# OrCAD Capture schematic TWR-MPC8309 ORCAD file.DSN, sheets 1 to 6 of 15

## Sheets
1 P15:Power Supplies: size C; title: Power Supplies; rev: C; note: TWR-MPC8309
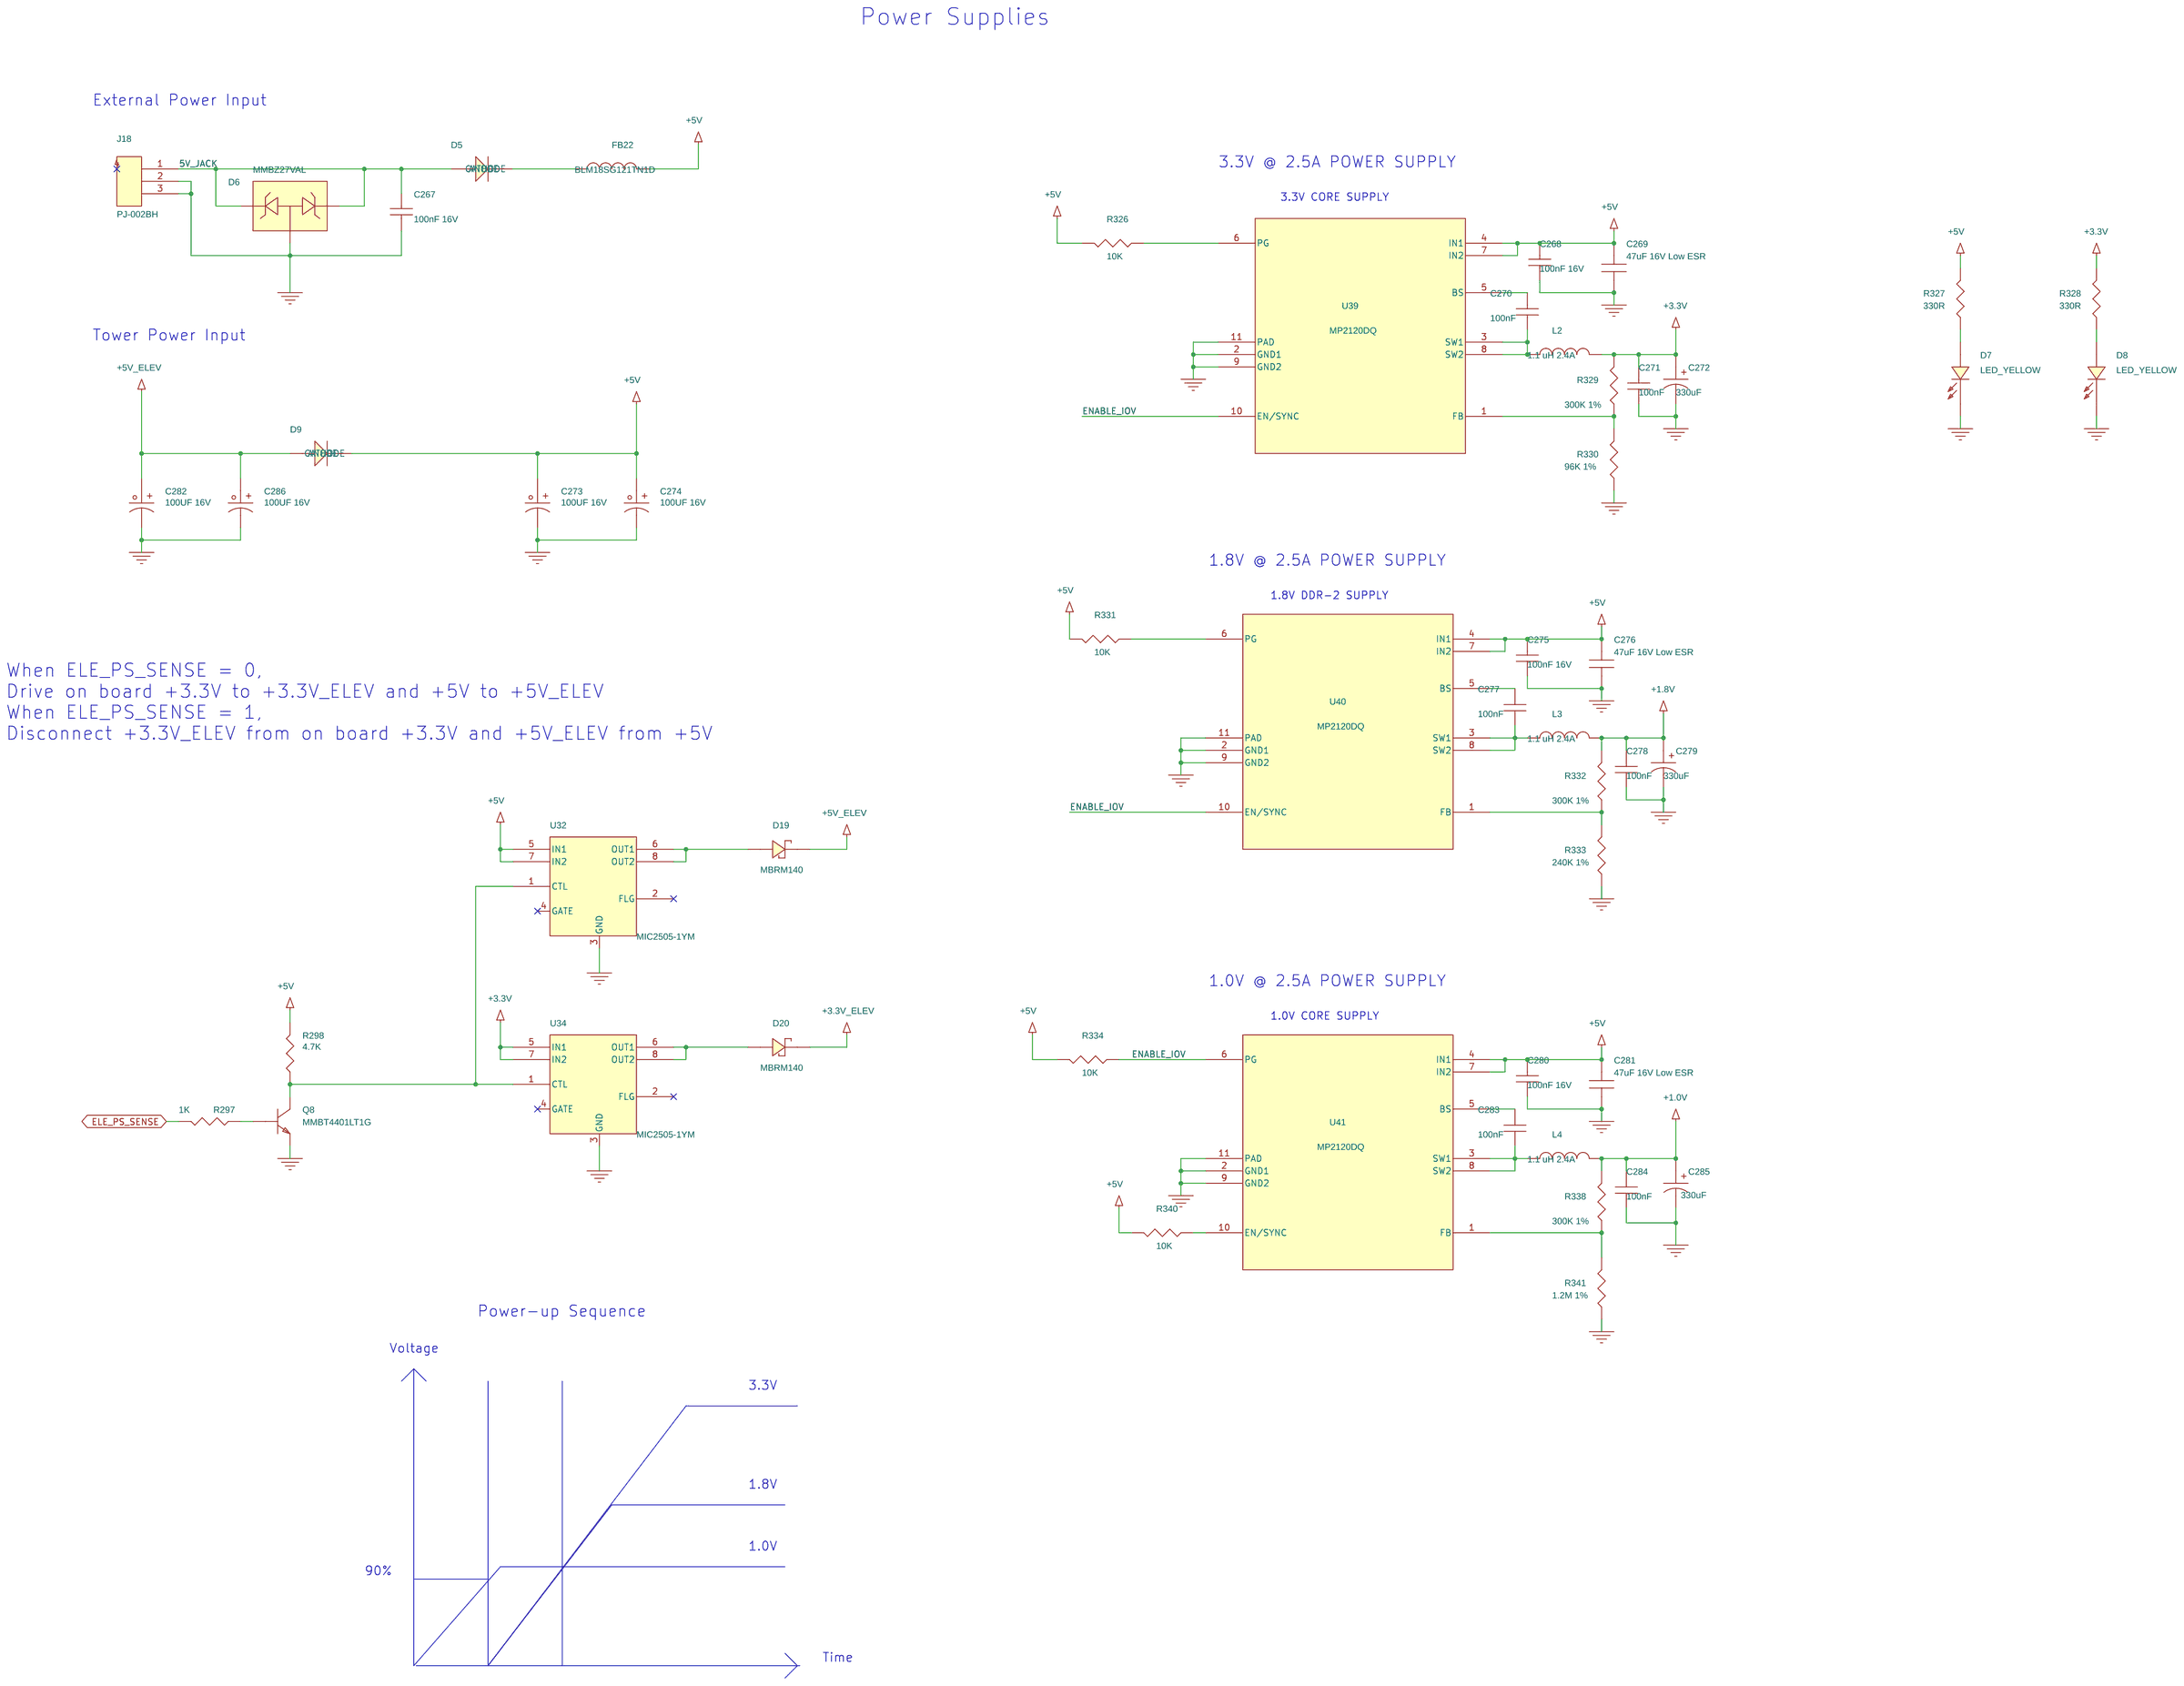
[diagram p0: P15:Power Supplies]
2 P13:Audio CODEC: size C; title: Audio CODEC
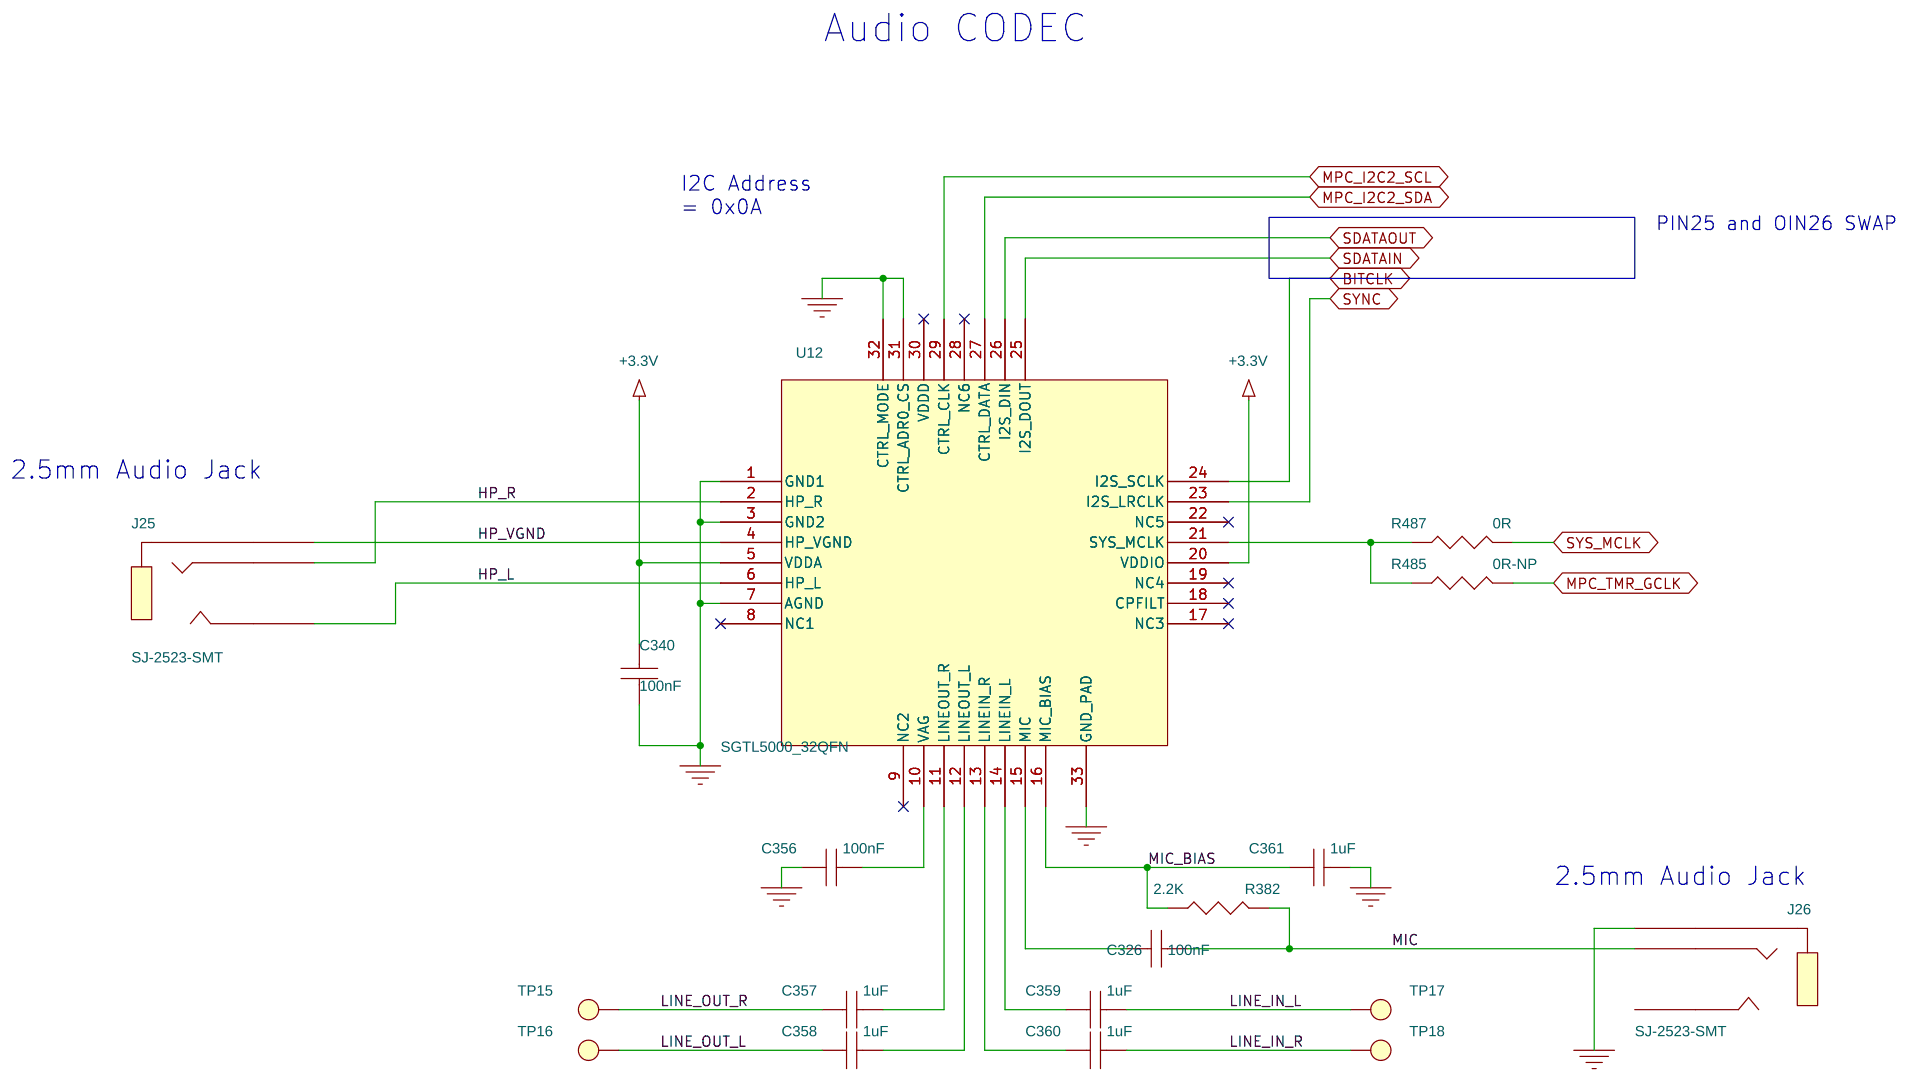
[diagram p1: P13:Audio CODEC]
3 P01:Cover Sheet: title: Cover page
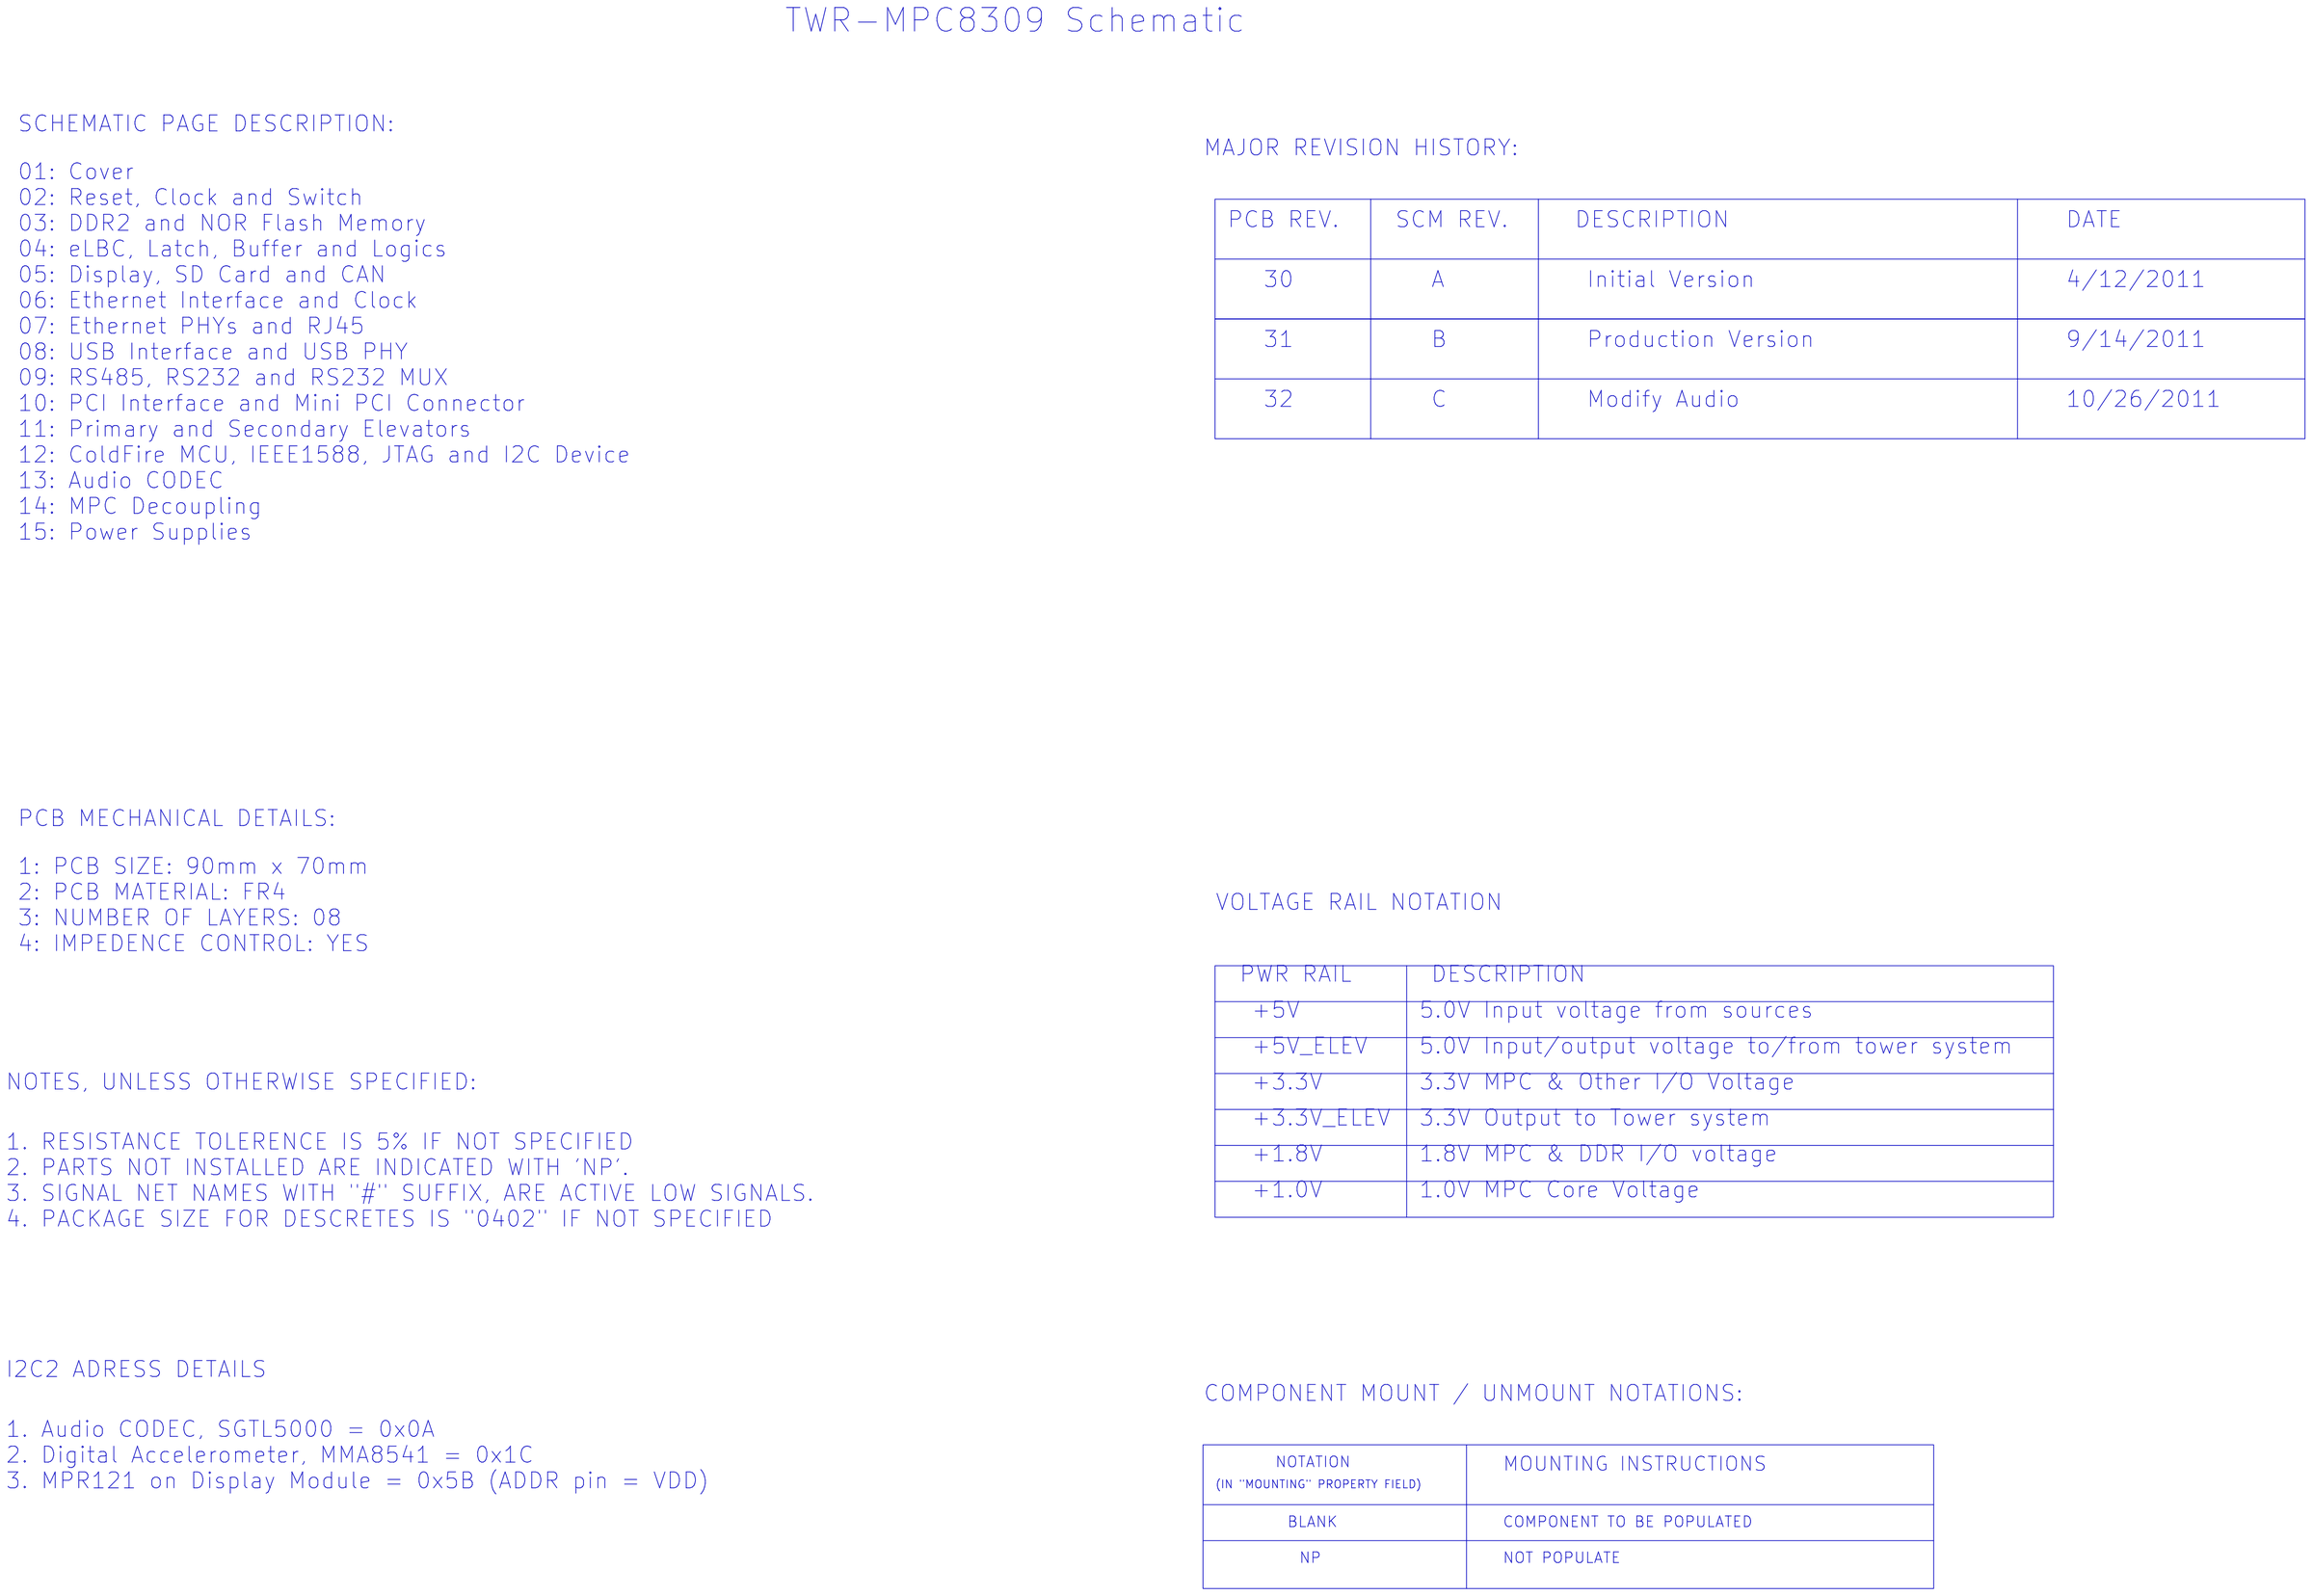
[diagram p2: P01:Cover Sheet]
4 P14:MPC Decoupling: size C; title: MPC Decoupling
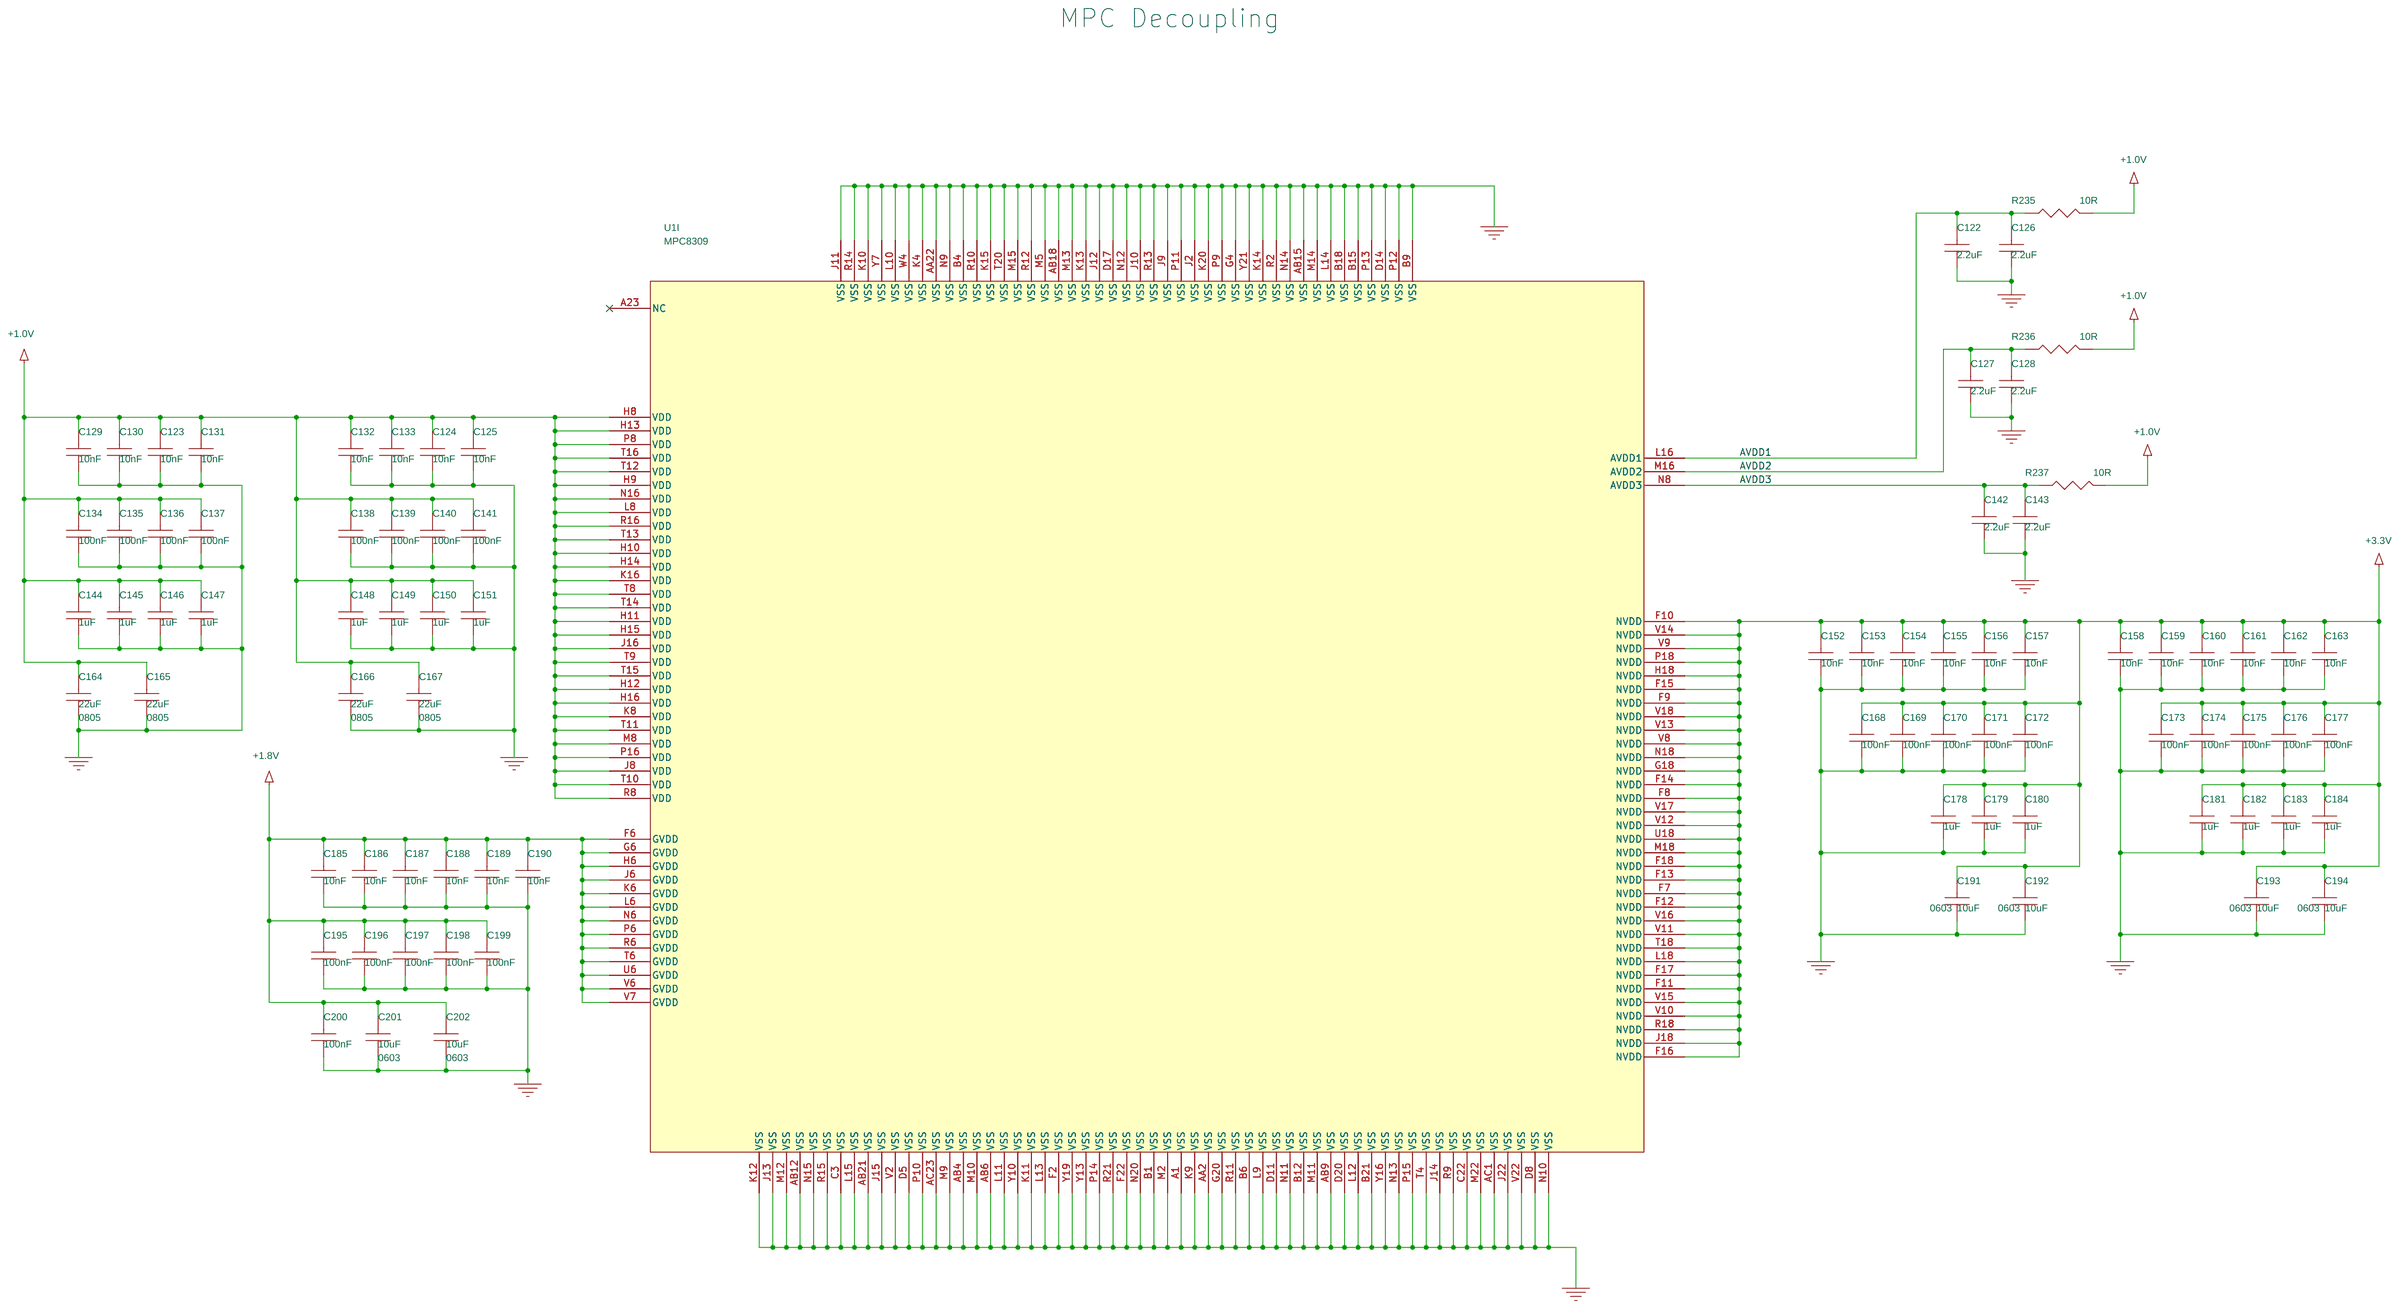
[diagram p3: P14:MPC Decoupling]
5 P05:Display, SD Card & CAN: size C; title: Display, SD card & CAN
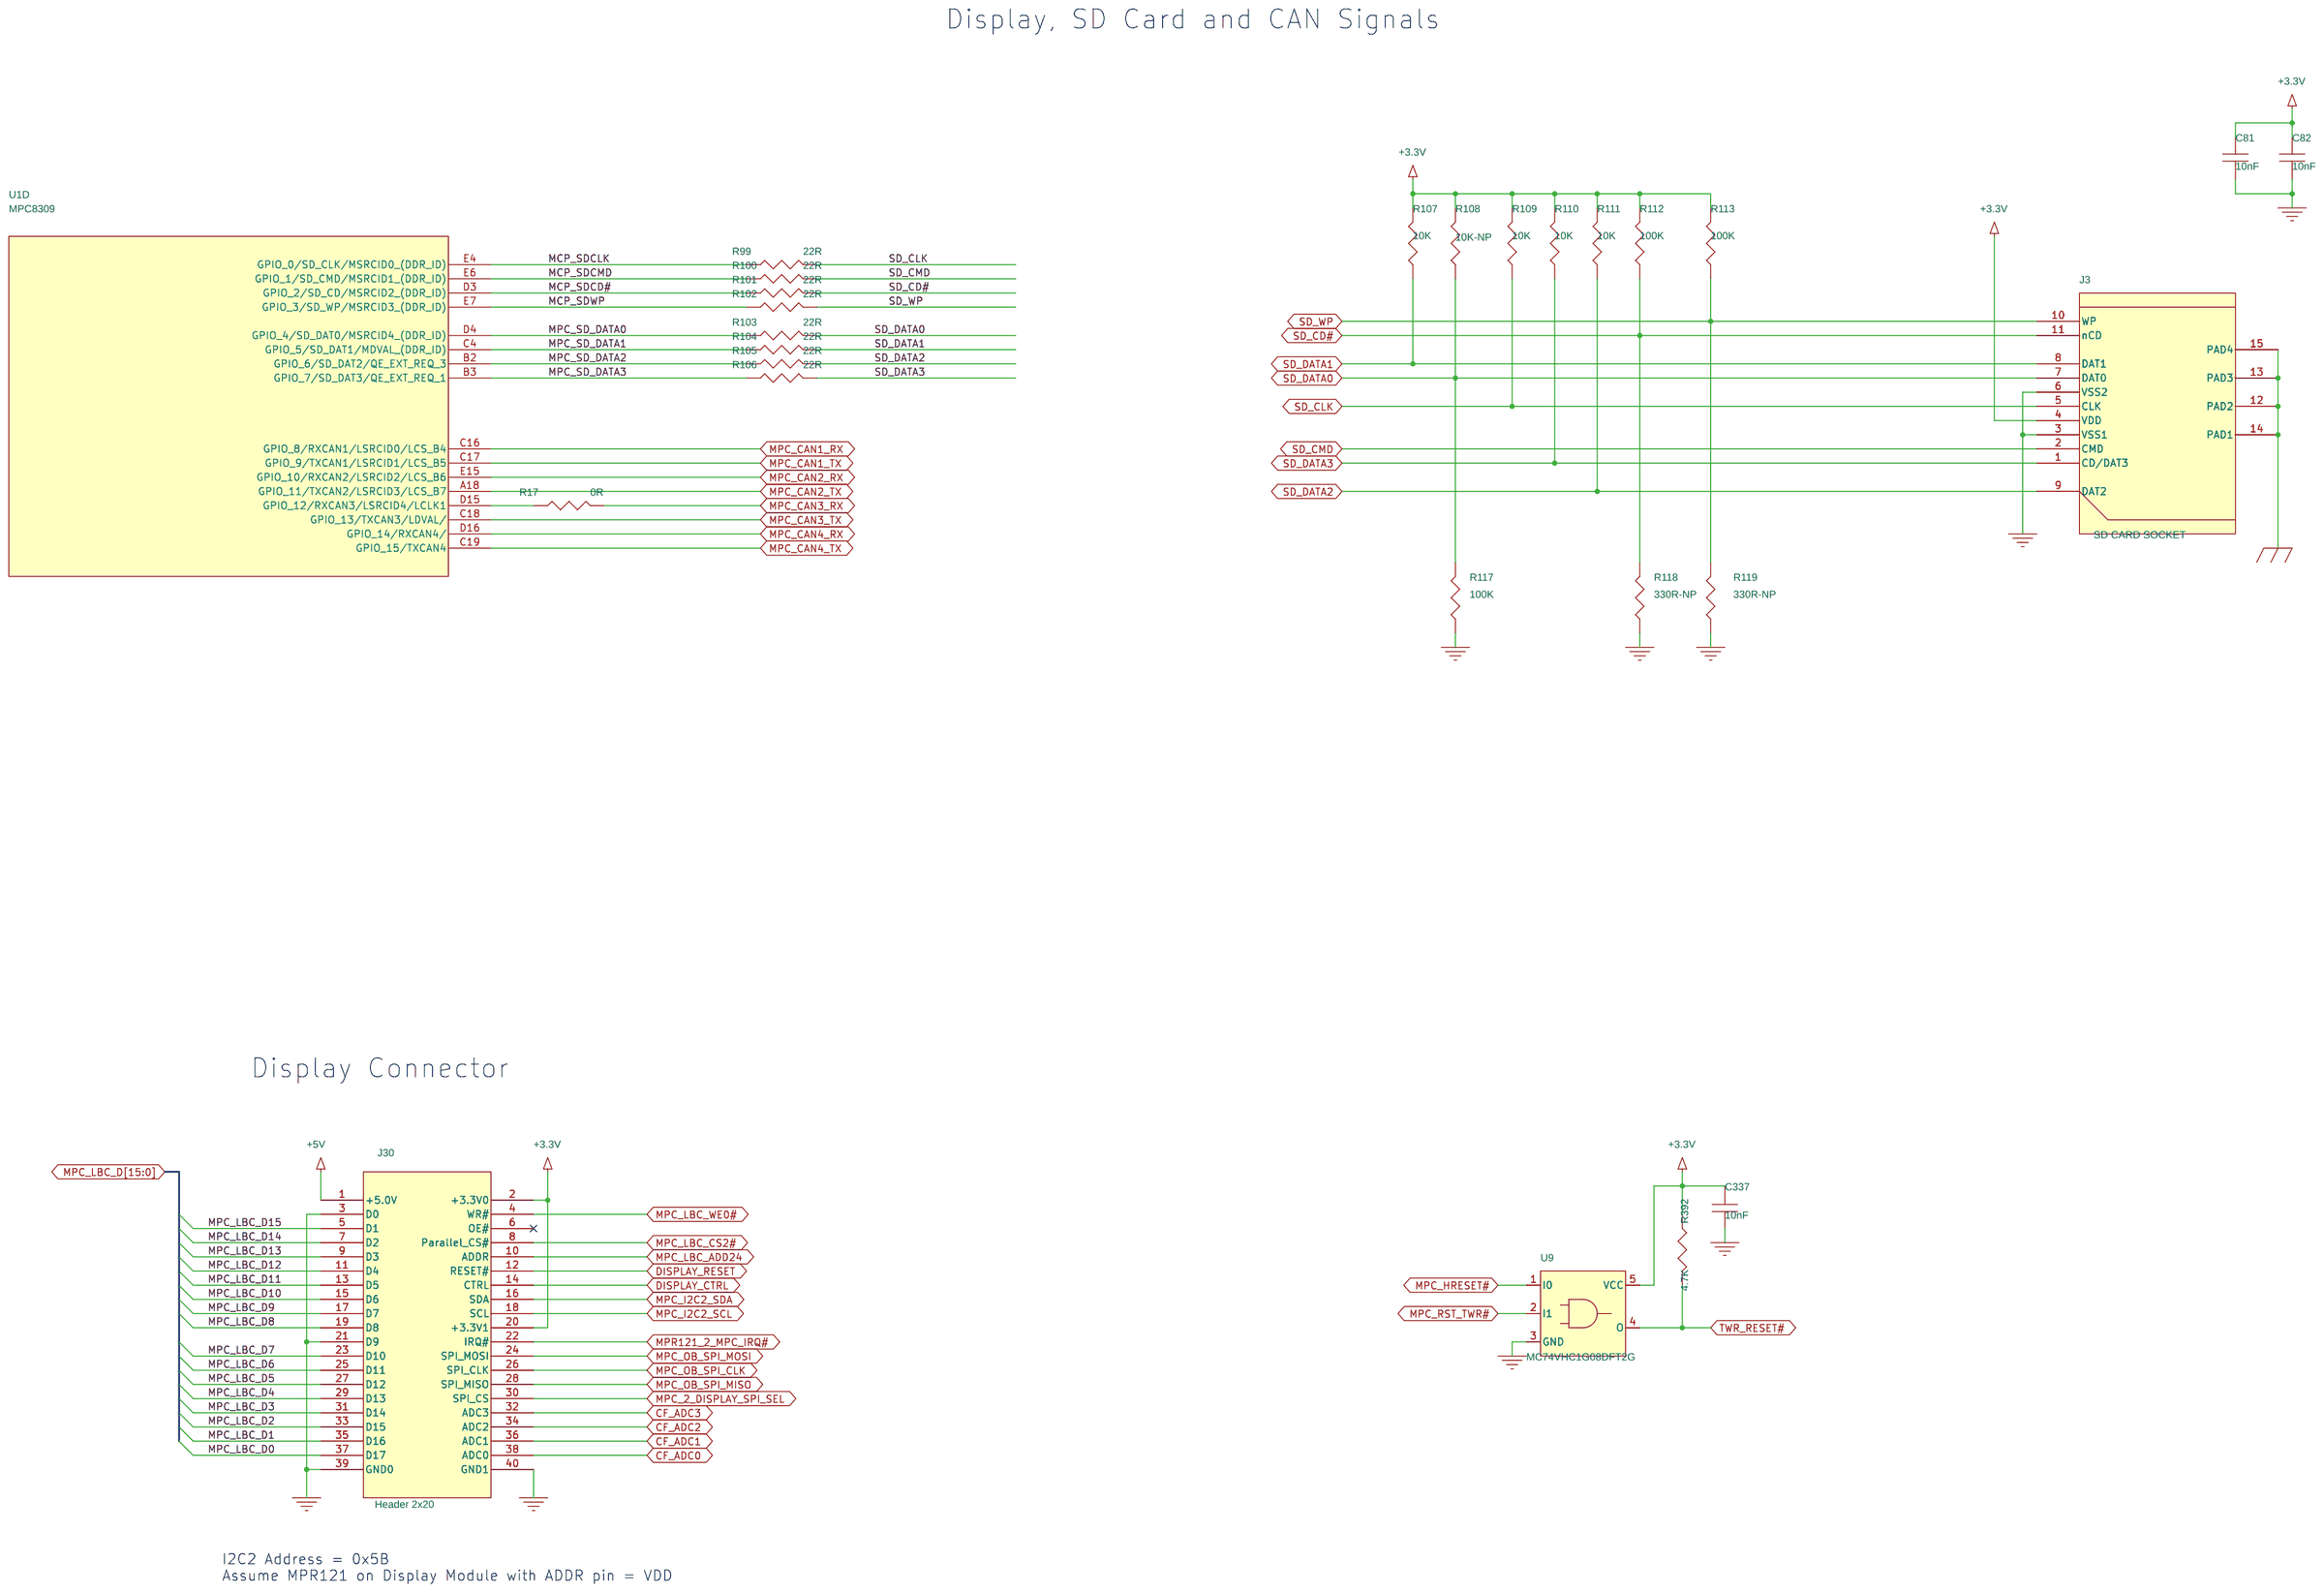
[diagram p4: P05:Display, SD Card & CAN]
6 P11:PRI & SEC Elevators: size C; title: Primary and Secondary Elevator
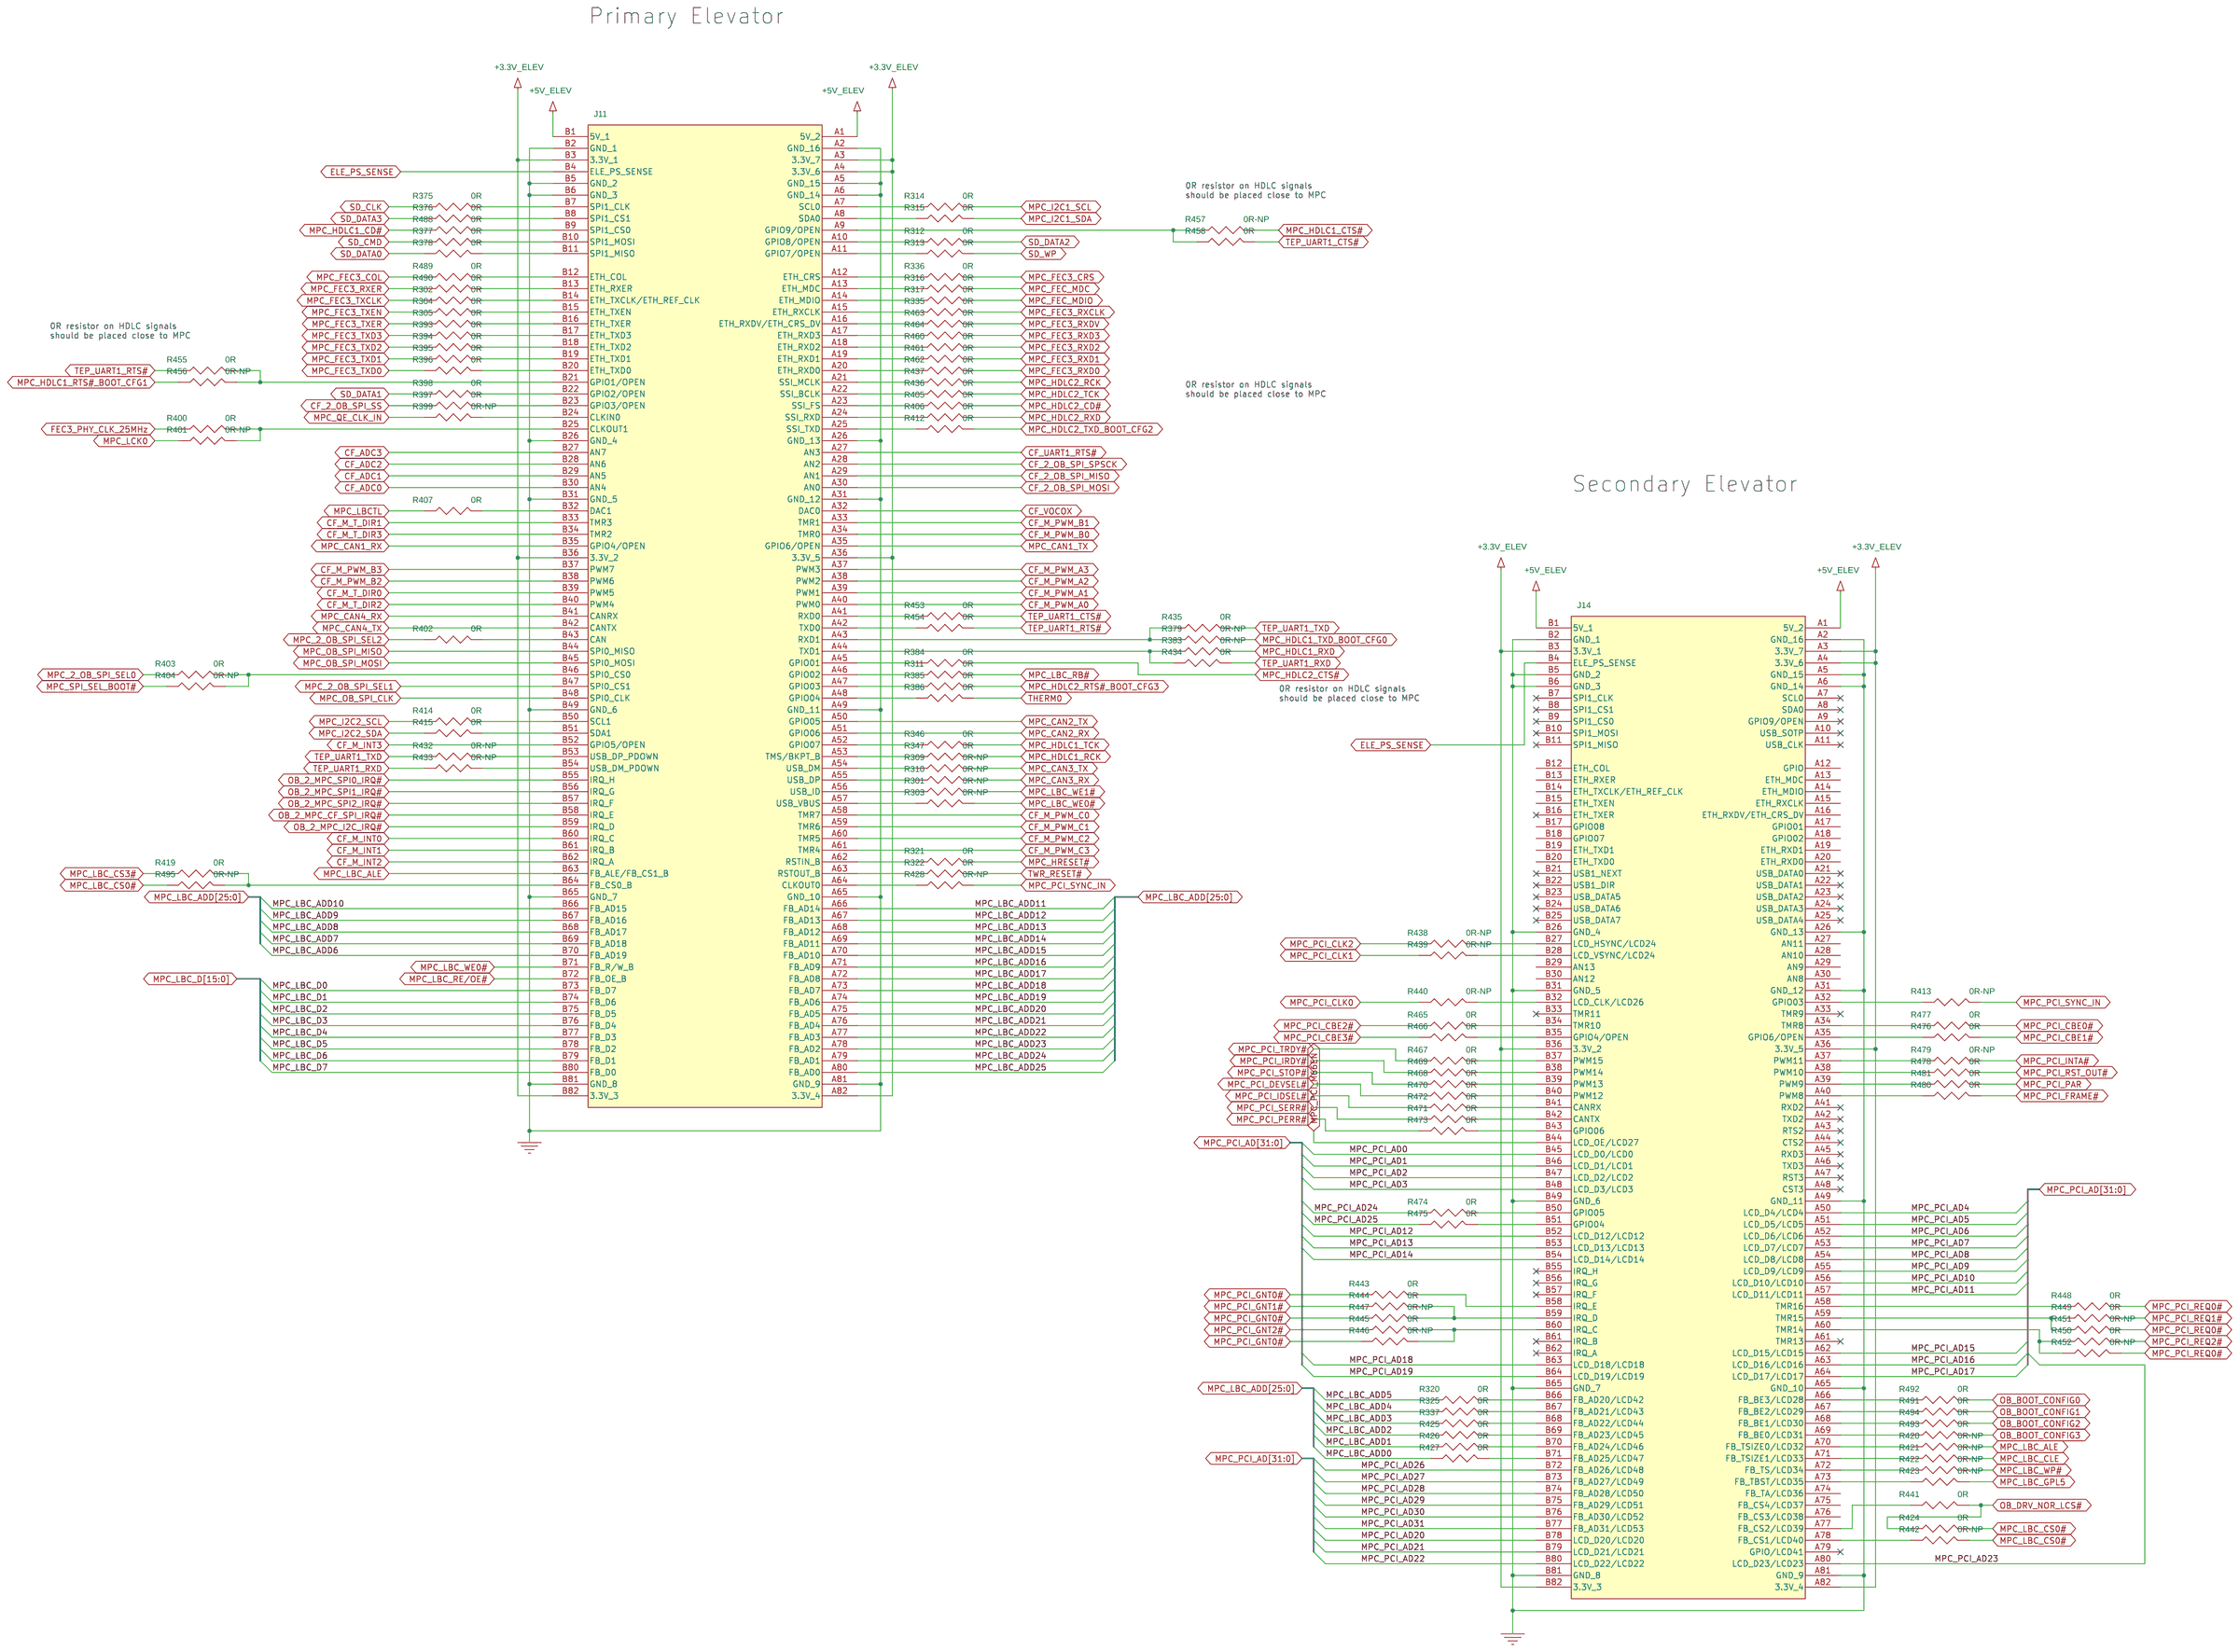
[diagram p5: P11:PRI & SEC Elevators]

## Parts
sheet P05:Display, SD Card & CAN
C81  10nF  [CC0402_CR]
C82  10nF  [CC0402_CR]
C337  10nF  [CC0402_CR]
J3  SD CARD SOCKET  [sd-card-25_5X16_6]
J30  Header 2x20  [header_2x20_05sp_smt_m]
R17  0R  [R0402_CR]
R99  22R  [R0402_CR]
R100  22R  [R0402_CR]
R101  22R  [R0402_CR]
R102  22R  [R0402_CR]
R103  22R  [R0402_CR]
R104  22R  [R0402_CR]
R105  22R  [R0402_CR]
R106  22R  [R0402_CR]
R107  10K  [R0402_CR]
R108  10K-NP  [R0402_CR]
R109  10K  [R0402_CR]
R110  10K  [R0402_CR]
R111  10K  [R0402_CR]
R112  100K  [R0402_CR]
R113  100K  [R0402_CR]
R117  100K  [R0402_CR]
R118  330R-NP  [R0402_CR]
R119  330R-NP  [R0402_CR]
R392  4.7K  [R0402_CR]
U9  MC74VHC1G08DFT2G  [SOT353]
sheet P11:PRI & SEC Elevators
J11  EDGE PCI EXPRESS 164  [con164_1mm_finger]
J14  EDGE PCI EXPRESS 164  [con164_1mm_finger]
R301  0R-NP  [R0402_CR]
R302  0R  [R0402_CR]
R303  0R-NP  [R0402_CR]
R304  0R  [R0402_CR]
R305  0R  [R0402_CR]
R309  0R-NP  [R0402_CR]
R310  0R-NP  [R0402_CR]
R311  0R  [R0402_CR]
R312  0R  [R0402_CR]
R313  0R  [R0402_CR]
R314  0R  [R0402_CR]
R315  0R  [R0402_CR]
R316  0R  [R0402_CR]
R317  0R  [R0402_CR]
R320  0R  [R0402_CR]
R321  0R  [R0402_CR]
R322  0R  [R0402_CR]
R325  0R  [R0402_CR]
R335  0R  [R0402_CR]
R336  0R  [R0402_CR]
R337  0R  [R0402_CR]
R346  0R  [R0402_CR]
R347  0R  [R0402_CR]
R375  0R  [R0402_CR]
R376  0R  [R0402_CR]
R377  0R  [R0402_CR]
R378  0R  [R0402_CR]
R379  0R-NP  [R0402_CR]
R383  0R-NP  [R0402_CR]
R384  0R  [R0402_CR]
R385  0R  [R0402_CR]
R386  0R  [R0402_CR]
R393  0R  [R0402_CR]
R394  0R  [R0402_CR]
R395  0R  [R0402_CR]
R396  0R  [R0402_CR]
R397  0R  [R0402_CR]
R398  0R  [R0402_CR]
R399  0R-NP  [R0402_CR]
R400  0R  [R0402_CR]
R401  0R-NP  [R0402_CR]
R402  0R  [R0402_CR]
R403  0R  [R0402_CR]
R404  0R-NP  [R0402_CR]
R405  0R  [R0402_CR]
R406  0R  [R0402_CR]
R407  0R  [R0402_CR]
R412  0R  [R0402_CR]
R413  0R-NP  [R0402_CR]
R414  0R  [R0402_CR]
R415  0R  [R0402_CR]
R419  0R  [R0402_CR]
R420  0R-NP  [R0402_CR]
R421  0R-NP  [R0402_CR]
R422  0R-NP  [R0402_CR]
R423  0R-NP  [R0402_CR]
R424  0R  [R0402_CR]
R425  0R  [R0402_CR]
R426  0R  [R0402_CR]
R427  0R  [R0402_CR]
R428  0R-NP  [R0402_CR]
R432  0R-NP  [R0402_CR]
R433  0R-NP  [R0402_CR]
R434  0R  [R0402_CR]
R435  0R  [R0402_CR]
R436  0R  [R0402_CR]
R437  0R  [R0402_CR]
R438  0R-NP  [R0402_CR]
R439  0R-NP  [R0402_CR]
R440  0R-NP  [R0402_CR]
R441  0R  [R0402_CR]
R442  0R-NP  [R0402_CR]
R443  0R  [R0402_CR]
R444  0R  [R0402_CR]
R445  0R  [R0402_CR]
R446  0R-NP  [R0402_CR]
R447  0R-NP  [R0402_CR]
R448  0R  [R0402_CR]
R449  0R  [R0402_CR]
R450  0R  [R0402_CR]
R451  0R-NP  [R0402_CR]
R452  0R-NP  [R0402_CR]
R453  0R  [R0402_CR]
R454  0R  [R0402_CR]
R455  0R  [R0402_CR]
R456  0R-NP  [R0402_CR]
R457  0R-NP  [R0402_CR]
R458  0R  [R0402_CR]
R460  0R  [R0402_CR]
R461  0R  [R0402_CR]
R462  0R  [R0402_CR]
R463  0R  [R0402_CR]
R464  0R  [R0402_CR]
R465  0R  [R0402_CR]
R466  0R  [R0402_CR]
R467  0R  [R0402_CR]
R468  0R  [R0402_CR]
R469  0R  [R0402_CR]
R470  0R  [R0402_CR]
R471  0R  [R0402_CR]
R472  0R  [R0402_CR]
R473  0R  [R0402_CR]
R474  0R  [R0402_CR]
R475  0R  [R0402_CR]
R476  0R  [R0402_CR]
R477  0R  [R0402_CR]
R478  0R  [R0402_CR]
R479  0R-NP  [R0402_CR]
R480  0R  [R0402_CR]
R481  0R  [R0402_CR]
R488  0R  [R0402_CR]
R489  0R  [R0402_CR]
R490  0R  [R0402_CR]
R491  0R  [R0402_CR]
R492  0R  [R0402_CR]
R493  0R  [R0402_CR]
R494  0R  [R0402_CR]
R495  0R-NP  [R0402_CR]
sheet P13:Audio CODEC
C326  100nF  [CC0402_CR]
C340  100nF  [CC0402_CR]
C356  100nF  [CC0402_CR]
C357  1uF  [CC0402_CR]
C358  1uF  [CC0402_CR]
C359  1uF  [CC0402_CR]
C360  1uF  [CC0402_CR]
C361  1uF  [CC0402_CR]
J25  SJ-2523-SMT  [2m5_jack]
J26  SJ-2523-SMT  [2m5_jack]
R382  2.2K  [R0402_CR]
R485  0R-NP  [R0402_CR]
R487  0R  [R0402_CR]
TP15  TP  [SMD_TP]
TP16  TP  [SMD_TP]
TP17  TP  [SMD_TP]
TP18  TP  [SMD_TP]
U12  SGTL5000_32QFN  [QFN32_5X5]
sheet P14:MPC Decoupling
C122  2.2uF  [CC0402_CR]
C123  10nF  [CC0402_CR]
C124  10nF  [CC0402_CR]
C125  10nF  [CC0402_CR]
C126  2.2uF  [CC0402_CR]
C127  2.2uF  [CC0402_CR]
C128  2.2uF  [CC0402_CR]
C129  10nF  [CC0402_CR]
C130  10nF  [CC0402_CR]
C131  10nF  [CC0402_CR]
C132  10nF  [CC0402_CR]
C133  10nF  [CC0402_CR]
C134  100nF  [CC0402_CR]
C135  100nF  [CC0402_CR]
C136  100nF  [CC0402_CR]
C137  100nF  [CC0402_CR]
C138  100nF  [CC0402_CR]
C139  100nF  [CC0402_CR]
C140  100nF  [CC0402_CR]
C141  100nF  [CC0402_CR]
C142  2.2uF  [CC0402_CR]
C143  2.2uF  [CC0402_CR]
C144  1uF  [CC0402_CR]
C145  1uF  [CC0402_CR]
C146  1uF  [CC0402_CR]
C147  1uF  [CC0402_CR]
C148  1uF  [CC0402_CR]
C149  1uF  [CC0402_CR]
C150  1uF  [CC0402_CR]
C151  1uF  [CC0402_CR]
C152  10nF  [CC0402_CR]
C153  10nF  [CC0402_CR]
C154  10nF  [CC0402_CR]
C155  10nF  [CC0402_CR]
C156  10nF  [CC0402_CR]
C157  10nF  [CC0402_CR]
C158  10nF  [CC0402_CR]
C159  10nF  [CC0402_CR]
C160  10nF  [CC0402_CR]
C161  10nF  [CC0402_CR]
C162  10nF  [CC0402_CR]
C163  10nF  [CC0402_CR]
C164  22uF  [CC0805]
C165  22uF  [CC0805]
C166  22uF  [CC0805]
C167  22uF  [CC0805]
C168  100nF  [CC0402_CR]
C169  100nF  [CC0402_CR]
C170  100nF  [CC0402_CR]
C171  100nF  [CC0402_CR]
C172  100nF  [CC0402_CR]
C173  100nF  [CC0402_CR]
C174  100nF  [CC0402_CR]
C175  100nF  [CC0402_CR]
C176  100nF  [CC0402_CR]
C177  100nF  [CC0402_CR]
C178  1uF  [CC0402_CR]
C179  1uF  [CC0402_CR]
C180  1uF  [CC0402_CR]
C181  1uF  [CC0402_CR]
C182  1uF  [CC0402_CR]
C183  1uF  [CC0402_CR]
C184  1uF  [CC0402_CR]
C185  10nF  [CC0402_CR]
C186  10nF  [CC0402_CR]
C187  10nF  [CC0402_CR]
C188  10nF  [CC0402_CR]
C189  10nF  [CC0402_CR]
C190  10nF  [CC0402_CR]
C191  10uF  [CC0603]
C192  10uF  [CC0603]
C193  10uF  [CC0603]
C194  10uF  [CC0603]
C195  100nF  [CC0402_CR]
C196  100nF  [CC0402_CR]
C197  100nF  [CC0402_CR]
C198  100nF  [CC0402_CR]
C199  100nF  [CC0402_CR]
C200  100nF  [CC0402_CR]
C201  10uF  [CC0603]
C202  10uF  [CC0603]
R235  10R  [R0402_CR]
R236  10R  [R0402_CR]
R237  10R  [R0402_CR]
U1  MPC8309  [MAPBGA489_80p]  (sections A,B,C,D,E,F,G,H,I)
sheet P15:Power Supplies
C267  100nF 16V  [CC0402_CR]
C268  100nF 16V  [CC0402_CR]
C269  47uF 16V Low ESR  [CC0805]
C270  100nF  [CC0402_CR]
C271  100nF  [CC0402_CR]
C272  330uF  [C7343]
C273  100UF 16V  [TC3528]
C274  100UF 16V  [TC3528]
C275  100nF 16V  [CC0402_CR]
C276  47uF 16V Low ESR  [CC0805]
C277  100nF  [CC0402_CR]
C278  100nF  [CC0402_CR]
C279  330uF  [C7343]
C280  100nF 16V  [CC0402_CR]
C281  47uF 16V Low ESR  [CC0805]
C282  100UF 16V  [TC3528]
C283  100nF  [CC0402_CR]
C284  100nF  [CC0402_CR]
C285  330uF  [C7343]
C286  100UF 16V  [TC3528]
D5  RB060M_30  [SOD_123]
D6  MMBZ27VAL  [SOT23-ACC]
D7  LED_YELLOW  [LED0603]
D8  LED_YELLOW  [LED0603]
D9  RB060M_30  [SOD_123]
D19  MBRM140  [CASE457-04]
D20  MBRM140  [CASE457-04]
FB22  BLM18SG121TN1D  [L0603]
J18  PJ-002BH  [DC-044]
L2  1.1 uH 2.4A  [VE5020]
L3  1.1 uH 2.4A  [VE5020]
L4  1.1 uH 2.4A  [VE5020]
Q8  MMBT4401LT1G  [SOT23]
R297  1K  [R0603B]
R298  4.7K  [R0603B]
R326  10K  [R0402_CR]
R327  330R  [R0402_CR]
R328  330R  [R0402_CR]
R329  300K 1%  [R0603B]
R330  96K 1%  [R0603B]
R331  10K  [R0402_CR]
R332  300K 1%  [R0603B]
R333  240K 1%  [R0603B]
R334  10K  [R0402_CR]
R338  300K 1%  [R0603B]
R340  10K  [R0402_CR]
R341  1.2M 1%  [R0603B]
U32  MIC2505-1YM  [SOIC127P600X173-8N]
U34  MIC2505-1YM  [SOIC127P600X173-8N]
U39  MP2120DQ  [QFN10_3x3]
U40  MP2120DQ  [QFN10_3x3]
U41  MP2120DQ  [QFN10_3x3]

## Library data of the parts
C81 C82 = CAP_NP_1: CAP CER 0.01UF 25V 10% X7R 0402; AGILE_PN: 150-75183; CAD_APPROVED: Yes; CLASS: discrete; HEIGHT: 0.5mm; MFG_NAME01: FENGHUA; MFG_PN01: 0402B103K250NTG; ROHS: Yes; Tolerance: 10%
C134-C141 C168-C177 C195-C200 C337 = CAP_NP: Mfg: Kemet; Mfg Part#: C0402C104K8PACTU; Oper. Temp. Range: -55°C ~ 85°C; Package: 0402; Price @ 100 pcs: 0.014; Price @ 10K: 0.0060; Price @ 1K: 0.0066; RoHS Compliant?: Yes; Specifications: CAP .10UF 10V CERAMIC X5R 0402; Vendor: Digikey; Vendor Part#: 399-3027-1-ND
J3 = SD_CARD_2: ROOM: SD
J30 = Header_2x20
R17 R382 = RESISTOR: Mfg: Yageo; Mfg Part#: RC0402FR-0722RL; Oper. Temp. Range: -55°C ~ 85°C; Package: 0402; Price @ 100 pcs: 0.066; Price @ 10K: 0.036; Price @ 1K: 0.00243; RoHS Compliant?: Yes; Specifications: RES 22.0 OHM 1/16W 1% 0402 SMD; Vendor: Digikey; Vendor Part#: 311-22.0LRCT-ND
R99-R106 R301-R305 R309-R317 R320-R322 R325 R335-R337 R346 R347 R375-R379 R383-R386 R393-R407 R412-R415 R419-R428 R432-R458 R460-R481 R485 R487-R495 = RESISTOR: Mfg: Yageo; Mfg Part#: RC0402FR-0722RL; Package: 0402; Price @ 100 pcs: 0.066; Price @ 10K: 0.036; Price @ 1K: 0.00243; RoHS Compliant?: Yes; Specifications: RES 22.0 OHM 1/16W 1% 0402 SMD; Vendor: Digikey; Vendor Part#: 311-22.0LRCT-ND
R107-R111 = R_4: RES MF 10K 1/16W 5% 0402; AGILE_PN: 470-75557; CAD_APPROVED: Yes; CLASS: Discrete; MFG_NAME01: VISHAY INTERTECHNOLOGY; MFG_PN01: CRCW040210K0JNED; ROHS: Yes; Tolerance: 5%
R112 R113 = R_4: RES MF 10K 1/16W 5% 0402; AGILE_PN: 470-75557; ASSY_OPT: DNP; CAD_APPROVED: Yes; CLASS: Discrete; MFG_NAME01: VISHAY INTERTECHNOLOGY; MFG_PN01: CRCW040210K0JNED; ROHS: Yes; Tolerance: 5%
R117 = R_4: RES MF 100K 1/10W 5% 0603; AGILE_PN: 470-75444; ASSY_OPT: DNP; CAD_APPROVED: Yes; CLASS: Discrete; MFG_NAME01: BOURNS; MFG_PN01: CR0603-JW-104ELF; ROHS: Yes; Tolerance: 5%
R118 R119 = R_4: RES MF 100K 1/10W 5% 0603; AGILE_PN: 470-75444; CAD_APPROVED: Yes; CLASS: Discrete; MFG_NAME01: BOURNS; MFG_PN01: CR0603-JW-104ELF; ROHS: Yes; Tolerance: 5%
R392 = RESISTOR: Mfg: Yageo; Mfg Part#: RC0402JR-074K7L; Oper. Temp. Range: -55°C ~ 85°C; Package: 0402; Price @ 100 pcs: 0.0066; Price @ 10K: 0.00213; Price @ 1K: 0.035; RoHS Compliant?: Yes; Specifications: RES 4.7K OHM 1/16W 5% 0402 SMD; Vendor: Digikey; Vendor Part#: 311-4.7KJRCT-ND
U9 = 74VHC1G08: IC GATE AND SGL 2-INPUT 2-5.5V SOT-353; AGILE_PN: 312-79604; CAD_APPROVED: Yes; CLASS: IC; HEIGHT: 1.1MM; MFG_NAME01: ON SEMICONDUCTOR; MFG_PN01: MC74VHC1G08DFT1G; ROHS: Yes
J11 = PCI_EXPRESSX16_2: CON 2X82 PCI EXPRESS X16 EDGE FOR ADD-IN CARD 1.0MM SP -- NO PART TO ORDER; AGILE_PN: 211-78698; CAD_APPROVED: Yes; HEIGHT: 0.1MM; MFG_NAME01: NA; MFG_PN01: NA; ROHS: Yes
J14 = PCI_EXPRESSX16_3: CON 2X82 PCI EXPRESS X16 EDGE FOR ADD-IN CARD 1.0MM SP -- NO PART TO ORDER; AGILE_PN: 211-78698; CAD_APPROVED: Yes; HEIGHT: 0.1MM; MFG_NAME01: NA; MFG_PN01: NA; ROHS: Yes
C326 C340 C356-C361 = CAP_NP: Mfg: Kemet; Mfg Part#: C0402C104K8PACTU; Package: 0402; RoHS Compliant?: Yes; Specifications: CAP .10UF 10V CERAMIC X5R 0402
J25 J26 = 3.5MM_STEREO_JACK
TP15-TP18 = TP: RoHS Compliant?: Yes
U12 = SGTL5000_32QFN
C122 C126-C128 C142 C143 = CAP_NP: Mfg: Taiyo Yuden; Mfg Part#: JMK105BJ225MV-F; Oper. Temp. Range: -55°C ~ 85°C; Package: 0402; Price @ 100 pcs: 0.156; Price @ 10K: 0.043; Price @ 1K: 0.0624; RoHS Compliant?: Yes; Specifications: CAP CER 2.2UF 6.3V X5R 0402; Vendor: Digikey; Vendor Part#: 587-1453-1-ND
C123-C125 C129-C133 C152-C163 C185-C190 = CAP_NP: Mfg: Yageo; Mfg Part#: CC0402KRX7R9BB103; Oper. Temp. Range: -55°C ~ 125°C; Package: 0402; Price @ 100 pcs: 0.006; Price @ 10K: 0.0018; Price @ 1K: 0.00268; RoHS Compliant?: Yes; Specifications: CAP CERAMIC .01UF 50V X7R 0402; Vendor: Digikey; Vendor Part#: 311-1349-1-ND
C144-C151 C178-C184 = CAP_NP: Mfg: Taiyo Yuden; Mfg Part#: JMK105BJ105KV-F; Oper. Temp. Range: -55°C ~ 85°C; Package: 0402; Price @ 100 pcs: 0.026; Price @ 10K: 0.0070; Price @ 1K: 0.0104; RoHS Compliant?: Yes; Specifications: CAP CER 1.0UF 6.3V X5R 0402; Vendor: Digikey; Vendor Part#: 587-1231-1-ND
C164-C167 = CAP_NP: Mfg: Taiyo Yuden; Mfg Part#: LMK212BJ226MG-T; Oper. Temp. Range: -55°C ~ 85°C; Package: 0805; Price @ 100 pcs: 0.42; Price @ 10K: 0.168; Price @ 1K: 0.30; RoHS Compliant?: Yes; Specifications: CAP CER 22UF 10V X5R 0805; Vendor: Digikey; Vendor Part#: 587-1958-1-ND
C191-C194 C201 C202 = CAP_NP: Mfg: Kemet; Mfg Part#: C0603C106M9PACTU; Oper. Temp. Range: -55°C ~ 85°C; Package: 0603; Price @ 100 pcs: 0.312; Price @ 10K: 0.105; Price @ 1K: 0.1248; RoHS Compliant?: Yes; Specifications: CAP CER 10UF 6.3V X5R 0603; Vendor: Digikey; Vendor Part#: 399-5504-1-ND
R235-R237 = RESISTOR: Mfg: Panasonic - ECG; Mfg Part#: ERJ-2GEJ100X; Oper. Temp. Range: -55°C ~ 85°C; Package: 0402; Price @ 100 pcs: 0.043; Price @ 10K: 0.017; Price @ 1K: 0.0050; RoHS Compliant?: Yes; Specifications: RES 10 OHM 1/10W 5% 0402 SMD; Vendor: Digikey; Vendor Part#: P10JCT-ND
U1 = IC_CPU_MPC8309_1: Mfg: Freescale; Mfg Part#: MPC8309CVMAFDCA; Package: MAPBGA; Price @ 100 pcs: 10; Price @ 10K: 10; Price @ 1K: 10; RoHS Compliant?: Yes; Specifications: PowerQUICC II Pro Integrated Communications Processor; Vendor: Freescale; Vendor Part#: MPC8309CVMAFDCA
C267 = DECAP: Cap, Ceramic, 0.1uF,50V, 10%, X7R, SMD0805; CLASS: DISCRETE; DEVICE: GC00-0R1050KX-0805; GDA Part No: GC00-0R1050KX-0805; Height: 1.25mm; Mfg: Panasonic; Mfg Part No: ECJ2FB1H104K; ROOM: POWER
C268 C275 C280 = DECAP: Cap, Chip, 390pF, 25V, 10%, SMD0402; CLASS: DISCRETE; DEVICE: GC00-391025KX-0402; GDA Part No: GC00-391025KX-0402; Height: 0.56mm; Mfg: Panasonic; Mfg Part No: ECJ0EB1E391K; ROOM: POWER
C269 C276 C281 = Cap_bulk_nonpol: Cap, 10uF, 20%, Cer-X5R, 16V, SMD, Size 0805; GDA Part No: GCX-R-00004502; Material: Cer-X5R; Mfg: AVX; Mfg Part No: 0805YD106MAT2A; Part Number: GCX-R-00004502; ROOM: POWER; Volts: 6.3V
C270 C271 C277 C278 C283 C284 = CAP: CCAP 1UF 0402; ROOM: POWER; device: CAP08; part number: 100000008; part type: SMT_CCAP; price: 0
C272 C279 C285 = CAP_POL_SMD_100uF_10V: Cap, Chip, 150uF,4V, 20%, SMD3528; 02 DESC: CAP ELECT 150uF 4V SMD; ROOM: POWER
C273 C274 C282 C286 = CAP_POL: CAP TANT ESR=1.2 0HM 100UF 10V 10% -- 6032-28; AGILE_PN: 150-76490; CAD_APPROVED: Yes; HEIGHT: 2.8 MM; MFG_NAME01: AVX; MFG_PN01: TAJC107K010R; ROHS: Yes; ROOM: POWER; Tolerance: 10%
D5 D9 = DIODE_0: DIODE PWR RECT 2A 600V 403A-03; AGILE_PN: 480-77641; CAD_APPROVED: Yes; HEIGHT: 2.45MM; MFG_NAME01: ON SEMICONDUCTOR; MFG_PN01: MURS060T3G; ROHS: Yes; ROOM: POWER
D6 = ESD_Protection_Diode_GSOT05C_0: Diode, MMBZ27VAL, 40W peak power, Dual Surface mount TVS, SOT-23; DEVICE: GD00-00000076-ST23; GDA Part No: GD00-00000076-ST23; Mfg: Diodes inc; ROOM: POWER
D7 D8 = LED: Mfg: Lumex; Mfg Part#: SML-LX0603GW-TR; Package: 0603; RoHS Compliant?: Yes; Specifications: LED 565NM GRN DIFF 0603 SMD
D19 D20 = SS12_SM_0: DIODE SCH PWR RECT 1A 40V --; AGILE_PN: 480-75196; CAD_APPROVED: YES; CLASS: Discrete; HEIGHT: 1.15 MM; MFG_NAME01: ON SEMICONDUCTOR; MFG_PN01: MBRM140T1G; ROHS: Yes
FB22 = INDUCTOR_0: Ferrite Bead, 2A, 140 OHMS, 1GHZ, SMD0603; Cost_Proto: 0.25; Cost_Vol: 0.14; Mfg: Murata; Mfg Part No: BLM18EG101TN1; Room: ETH
J18 = PJ-002BH_0: CLASS: IO; ROOM: POWER
L2-L4 = INDUCTOR: Inductor, CDRH4D18C, 1.1uF, 2.4A, SMT; CLASS: DISCRETE; DEVICE: GL00-1R100002-0000; GDA Part No: GL00-1R100002-0000; Height: 0.85mm; Mfg: Sumida; Mfg Part No: CDRH4D18C1R1; ROOM: POWER
Q8 = MMBT4401LT1: TRAN NPN SW 600MA 40V SOT23; AGILE_PN: 480-75087; CAD_APPROVED: Yes; Class: Discrete; HEIGHT: 1.11MM; MFG_NAME01: ON SEMICONDUCTOR; ROHS: Yes
R297 = R_0: RES MF 1.0K 1/8W 5% 0805; AGILE_PN: 470-75989; CAD_APPROVED: Yes; CLASS: Discrete; MFG_NAME01: ROHM; MFG_PN01: MCR10EZHJ102; ROHS: Yes; Tolerance: 5%
R298 = R_4: RES MF 100 OHM 1/16W 5% 0402; AGILE_PN: 470-75591; CAD_APPROVED: Yes; CLASS: Discrete; MFG_NAME01: VISHAY INTERTECHNOLOGY; MFG_PN01: CRCW0402100RJNED; ROHS: Yes; Tolerance: 5%
R326 R331 R334 R340 = RESISTOR: FPLIST: R0402; ROOM: POWER
R327-R330 R332 R333 = Res: Res, 100K, 1%, Chip, 0.063W, SMD, Size 0402; FPLIST: R0402; GDA Part No: GRX-R-00000037; Mfg: KOA; Mfg Part No: RK73H1ETTP1003F; Part Number: GRX-R-00000037; ROOM: POWER; Sub_Type: Chip; Tolerance: 1%
R338 R341 = Res: Res, 100K, 1%, Chip, 0.063W, SMD, Size 0402; GDA Part No: GRX-R-00000037; Mfg: KOA; Mfg Part No: RK73H1ETTP1003F; Part Number: GRX-R-00000037; ROOM: POWER; Sub_Type: Chip; Tolerance: 1%
U32 U34 = MIC2505BM: Mfg: Micrel; Package: SOIC-8; RoHS Compliant?: Yes; Specifications: IC SW HIGH SIDE SGL 2A 8SOIC
U39-U41 = NB636_4: IC,MP2120; ROOM: POWER

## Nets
5V_JACK: C267.1 D5.1(CATHODE) D6.2 D6.3 J18.1
+1.0V: C123.2 C124.2 C125.2 C129.2 C130.2 C131.2 C132.2 C133.2 C134.2 C135.2 C136.2 C137.2 C138.2 C139.2 C140.2 C141.2 C144.2 C145.2 C146.2 C147.2 C148.2 C149.2 C150.2 C151.2 C164.2 C165.2 C166.2 C167.2 C284.2 C285.1 L4.1 R235.2 R236.2 R237.2 R338.2 U1.H8(VDD) U1.H9(VDD) U1.H10(VDD) U1.H11(VDD) U1.H12(VDD) U1.H13(VDD) U1.H14(VDD) U1.H15(VDD) U1.H16(VDD) U1.J8(VDD) U1.J16(VDD) U1.K8(VDD) U1.K16(VDD) U1.L8(VDD) U1.M8(VDD) U1.N16(VDD) U1.P8(VDD) U1.P16(VDD) U1.R8(VDD) U1.R16(VDD) U1.T8(VDD) U1.T9(VDD) U1.T10(VDD) U1.T11(VDD) U1.T12(VDD) U1.T13(VDD) U1.T14(VDD) U1.T15(VDD) U1.T16(VDD)
+1.8V: C185.2 C186.2 C187.2 C188.2 C189.2 C190.2 C195.2 C196.2 C197.2 C198.2 C199.2 C200.2 C201.2 C202.2 C278.2 C279.1 L3.1 R332.2 U1.F6(GVDD) U1.G6(GVDD) U1.H6(GVDD) U1.J6(GVDD) U1.K6(GVDD) U1.L6(GVDD) U1.N6(GVDD) U1.P6(GVDD) U1.R6(GVDD) U1.T6(GVDD) U1.U6(GVDD) U1.V6(GVDD) U1.V7(GVDD) ; also on sheet 10
+3.3V: C81.1 C82.1 C152.2 C153.2 C154.2 C155.2 C156.2 C157.2 C158.2 C159.2 C160.2 C161.2 C162.2 C163.2 C168.2 C169.2 C170.2 C171.2 C172.2 C173.2 C174.2 C175.2 C176.2 C177.2 C178.2 C179.2 C180.2 C181.2 C182.2 C183.2 C184.2 C191.2 C192.2 C193.2 C194.2 C271.2 C272.1 C337.2 C340.1 J3.4(VDD) J30.2(+3.3V0) J30.20(+3.3V1) L2.1 R107.1 R108.1 R109.1 R110.1 R111.1 R112.1 R113.1 R328.2 R329.2 R392.1 U1.F7(NVDD) U1.F8(NVDD) U1.F9(NVDD) U1.F10(NVDD) U1.F11(NVDD) U1.F12(NVDD) U1.F13(NVDD) U1.F14(NVDD) U1.F15(NVDD) U1.F16(NVDD) U1.F17(NVDD) U1.F18(NVDD) U1.G18(NVDD) U1.H18(NVDD) U1.J18(NVDD) U1.L18(NVDD) U1.M18(NVDD) U1.N18(NVDD) U1.P18(NVDD) U1.R18(NVDD) U1.T18(NVDD) U1.U18(NVDD) U1.V8(NVDD) U1.V9(NVDD) U1.V10(NVDD) U1.V11(NVDD) U1.V12(NVDD) U1.V13(NVDD) U1.V14(NVDD) U1.V15(NVDD) U1.V16(NVDD) U1.V17(NVDD) U1.V18(NVDD) U9.5(VCC) U12.5(VDDA) U12.20(VDDIO) U34.5(IN1) U34.7(IN2) ; also on sheet 7 8 9 10 11 12 13 14 15
+3.3V_ELEV: D20.1(CATHODE) J11.A3(3.3V_7) J11.A4(3.3V_6) J11.A36(3.3V_5) J11.A82(3.3V_4) J11.B3(3.3V_1) J11.B36(3.3V_2) J11.B82(3.3V_3) J14.A3(3.3V_7) J14.A4(3.3V_6) J14.A36(3.3V_5) J14.A82(3.3V_4) J14.B3(3.3V_1) J14.B36(3.3V_2) J14.B82(3.3V_3)
+5V: C268.2 C269.1 C273.1 C274.1 C275.2 C276.1 C280.2 C281.1 D9.2(ANODE) FB22.1 J30.1(+5.0V) R298.1 R326.2 R327.2 R331.2 R334.2 R340.2 U32.5(IN1) U32.7(IN2) U39.4(IN1) U39.7(IN2) U40.4(IN1) U40.7(IN2) U41.4(IN1) U41.7(IN2) ; also on sheet 9 11 12 15
+5V_ELEV: C282.1 C286.1 D9.1(CATHODE) D19.1(CATHODE) J11.A1(5V_2) J11.B1(5V_1) J14.A1(5V_2) J14.B1(5V_1)
AVDD1: C122.2 C126.2 R235.1 U1.L16(AVDD1)
AVDD2: C127.2 C128.2 R236.1 U1.M16(AVDD2)
AVDD3: C142.2 C143.2 R237.1 U1.N8(AVDD3)
GND: C81.2 C82.2 C122.1 C123.1 C124.1 C125.1 C126.1 C127.1 C128.1 C129.1 C130.1 C131.1 C132.1 C133.1 C134.1 C135.1 C136.1 C137.1 C138.1 C139.1 C140.1 C141.1 C142.1 C143.1 C144.1 C145.1 C146.1 C147.1 C148.1 C149.1 C150.1 C151.1 C152.1 C153.1 C154.1 C155.1 C156.1 C157.1 C158.1 C159.1 C160.1 C161.1 C162.1 C163.1 C164.1 C165.1 C166.1 C167.1 C168.1 C169.1 C170.1 C171.1 C172.1 C173.1 C174.1 C175.1 C176.1 C177.1 C178.1 C179.1 C180.1 C181.1 C182.1 C183.1 C184.1 C185.1 C186.1 C187.1 C188.1 C189.1 C190.1 C191.1 C192.1 C193.1 C194.1 C195.1 C196.1 C197.1 C198.1 C199.1 C200.1 C201.1 C202.1 C267.2 C268.1 C269.2 C271.1 C272.2 C273.2 C274.2 C275.1 C276.2 C278.1 C279.2 C280.1 C281.2 C282.2 C284.1 C285.2 C286.2 C337.1 C340.2 C356.1 C361.2 D6.1 D7.2(CATHODE) D8.2(CATHODE) J3.3(VSS1) J3.6(VSS2) J11.A2(GND_16) J11.A5(GND_15) J11.A6(GND_14) J11.A26(GND_13) J11.A31(GND_12) J11.A49(GND_11) J11.A65(GND_10) J11.A81(GND_9) J11.B2(GND_1) J11.B5(GND_2) J11.B6(GND_3) J11.B26(GND_4) J11.B31(GND_5) J11.B49(GND_6) J11.B65(GND_7) J11.B81(GND_8) J14.A2(GND_16) J14.A5(GND_15) J14.A6(GND_14) J14.A26(GND_13) J14.A31(GND_12) J14.A49(GND_11) J14.A65(GND_10) J14.A81(GND_9) J14.B2(GND_1) J14.B5(GND_2) J14.B6(GND_3) J14.B26(GND_4) J14.B31(GND_5) J14.B49(GND_6) J14.B65(GND_7) J14.B81(GND_8) J18.2 J18.3 J26.1 J30.3(D0) J30.21(D9) J30.39(GND0) J30.40(GND1) Q8.2(EMITTER) R117.2 R118.2 R119.2 R330.1 R333.1 R341.1 U1.A1(VSS) U1.AA2(VSS) U1.AA22(VSS) U1.AB4(VSS) U1.AB6(VSS) U1.AB9(VSS) U1.AB12(VSS) U1.AB15(VSS) U1.AB18(VSS) U1.AB21(VSS) U1.AC1(VSS) U1.AC23(VSS) U1.B1(VSS) U1.B4(VSS) U1.B6(VSS) U1.B9(VSS) U1.B12(VSS) U1.B15(VSS) U1.B18(VSS) U1.B21(VSS) U1.C3(VSS) U1.C22(VSS) U1.D5(VSS) U1.D8(VSS) U1.D11(VSS) U1.D14(VSS) U1.D17(VSS) U1.D20(VSS) U1.F2(VSS) U1.F22(VSS) U1.G4(VSS) U1.G20(VSS) U1.J2(VSS) U1.J9(VSS) U1.J10(VSS) U1.J11(VSS) U1.J12(VSS) U1.J13(VSS) U1.J14(VSS) U1.J15(VSS) U1.J22(VSS) U1.K4(VSS) U1.K9(VSS) U1.K10(VSS) U1.K11(VSS) U1.K12(VSS) U1.K13(VSS) U1.K14(VSS) U1.K15(VSS) U1.K20(VSS) U1.L9(VSS) U1.L10(VSS) U1.L11(VSS) U1.L12(VSS) U1.L13(VSS) U1.L14(VSS) U1.L15(VSS) U1.M2(VSS) U1.M5(VSS) U1.M9(VSS) U1.M10(VSS) U1.M11(VSS) U1.M12(VSS) U1.M13(VSS) U1.M14(VSS) U1.M15(VSS) U1.M22(VSS) U1.N9(VSS) U1.N10(VSS) U1.N11(VSS) U1.N12(VSS) U1.N13(VSS) U1.N14(VSS) U1.N15(VSS) U1.N20(VSS) U1.P9(VSS) U1.P10(VSS) U1.P11(VSS) U1.P12(VSS) U1.P13(VSS) U1.P14(VSS) U1.P15(VSS) U1.R2(VSS) U1.R9(VSS) U1.R10(VSS) U1.R11(VSS) U1.R12(VSS) U1.R13(VSS) U1.R14(VSS) U1.R15(VSS) U1.R21(VSS) U1.T4(VSS) U1.T20(VSS) U1.V2(VSS) U1.V22(VSS) U1.W4(VSS) U1.Y7(VSS) U1.Y10(VSS) U1.Y13(VSS) U1.Y16(VSS) U1.Y19(VSS) U1.Y21(VSS) U9.3(GND) U12.1(GND1) U12.3(GND2) U12.7(AGND) U12.31(CTRL_ADR0_CS) U12.32(CTRL_MODE) U12.33(GND_PAD) U32.3(GND) U34.3(GND) U39.2(GND1) U39.9(GND2) U39.11(PAD) U40.2(GND1) U40.9(GND2) U40.11(PAD) U41.2(GND1) U41.9(GND2) U41.11(PAD) ; also on sheet 7 8 9 10 11 12 13 14 15
GND_EARTH: J3.12(PAD2) J3.13(PAD3) J3.14(PAD1) J3.15(PAD4) ; also on sheet 7 9
BITCLK: U12.24(I2S_SCLK) ; also on sheet 15
CF_2_OB_SPI_MISO: J11.A29(AN1) ; also on sheet 15
CF_2_OB_SPI_MOSI: J11.A30(AN0) ; also on sheet 15
CF_2_OB_SPI_SPSCK: J11.A28(AN2) ; also on sheet 15
CF_2_OB_SPI_SS: R397.1 ; also on sheet 15
CF_ADC0: J11.B30(AN4) J30.38(ADC0) ; also on sheet 15
CF_ADC1: J11.B29(AN5) J30.36(ADC1) ; also on sheet 15
CF_ADC2: J11.B28(AN6) J30.34(ADC2) ; also on sheet 15
CF_ADC3: J11.B27(AN7) J30.32(ADC3) ; also on sheet 15
CF_M_INT0: J11.B60(IRQ_C) ; also on sheet 15
CF_M_INT1: J11.B61(IRQ_B) ; also on sheet 15
CF_M_INT2: J11.B62(IRQ_A) ; also on sheet 15
CF_M_INT3: J11.B52(GPIO5/OPEN) ; also on sheet 15
CF_M_PWM_A0: J11.A40(PWM0) ; also on sheet 15
CF_M_PWM_A1: J11.A39(PWM1) ; also on sheet 15
CF_M_PWM_A2: J11.A38(PWM2) ; also on sheet 15
CF_M_PWM_A3: J11.A37(PWM3) ; also on sheet 15
CF_M_PWM_B0: J11.A34(TMR0) ; also on sheet 15
CF_M_PWM_B1: J11.A33(TMR1) ; also on sheet 15
CF_M_PWM_B2: J11.B38(PWM6) ; also on sheet 15
CF_M_PWM_B3: J11.B37(PWM7) ; also on sheet 15
CF_M_PWM_C0: J11.A58(TMR7) ; also on sheet 15
CF_M_PWM_C1: J11.A59(TMR6) ; also on sheet 15
CF_M_PWM_C2: J11.A60(TMR5) ; also on sheet 15
CF_M_PWM_C3: J11.A61(TMR4) ; also on sheet 15
CF_M_T_DIR0: J11.B39(PWM5) ; also on sheet 15
CF_M_T_DIR1: J11.B33(TMR3) ; also on sheet 15
CF_M_T_DIR2: J11.B40(PWM4) ; also on sheet 15
CF_M_T_DIR3: J11.B34(TMR2) ; also on sheet 15
CF_UART1_RTS#: J11.A27(AN3) ; also on sheet 12 15
CF_VOCOX: J11.A32(DAC0) ; also on sheet 8 15
DISPLAY_CTRL: J30.14(CTRL) ; also on sheet 13
DISPLAY_RESET: J30.12(RESET#) ; also on sheet 13
ELE_PS_SENSE: J11.B4(ELE_PS_SENSE) J14.B4(ELE_PS_SENSE) R297.2
ENABLE_IOV: R334.1 U39.10(EN/SYNC) U40.10(EN/SYNC) U41.6(PG)
FEC3_PHY_CLK_25MHz: R400.1 ; also on sheet 14
HP_L: J25.2 U12.6(HP_L)
HP_R: J25.3 U12.2(HP_R)
HP_VGND: J25.1 U12.4(HP_VGND)
LINE_IN_L: C359.2 TP17.1(TP)
LINE_IN_R: C360.2 TP18.1(TP)
LINE_OUT_L: C358.1 TP16.1(TP)
LINE_OUT_R: C357.1 TP15.1(TP)
MCP_SDCD#: R101.1 U1.D3(GPIO_2/SD_CD/MSRCID2_(DDR_ID))
MCP_SDCLK: R99.1 U1.E4(GPIO_0/SD_CLK/MSRCID0_(DDR_ID))
MCP_SDCMD: R100.1 U1.E6(GPIO_1/SD_CMD/MSRCID1_(DDR_ID))
MCP_SDWP: R102.1 U1.E7(GPIO_3/SD_WP/MSRCID3_(DDR_ID))
MIC: C326.2 J26.3 R382.1
MIC_BIAS: C361.1 R382.2 U12.16(MIC_BIAS)
MPC_2_DISPLAY_SPI_SEL: J30.30(SPI_CS) ; also on sheet 13
MPC_2_OB_SPI_SEL0: R403.1 ; also on sheet 13
MPC_2_OB_SPI_SEL1: J11.B47(SPI0_CS1) ; also on sheet 13
MPC_2_OB_SPI_SEL2: R402.1 ; also on sheet 13
MPC_CAN1_RX: J11.B35(GPIO4/OPEN) U1.C16(GPIO_8/RXCAN1/LSRCID0/LCS_B4)
MPC_CAN1_TX: J11.A35(GPIO6/OPEN) U1.C17(GPIO_9/TXCAN1/LSRCID1/LCS_B5)
MPC_CAN2_RX: J11.A51(GPIO06) U1.E15(GPIO_10/RXCAN2/LSRCID2/LCS_B6)
MPC_CAN2_TX: J11.A50(GPIO05) U1.A18(GPIO_11/TXCAN2/LSRCID3/LCS_B7)
MPC_CAN3_RX: R17.2 R310.2 ; also on sheet 14
MPC_CAN3_TX: R309.2 U1.C18(GPIO_13/TXCAN3/LDVAL/)
MPC_CAN4_RX: J11.B41(CANRX) U1.D16(GPIO_14/RXCAN4/)
MPC_CAN4_TX: J11.B42(CANTX) U1.C19(GPIO_15/TXCAN4)
MPC_FEC3_COL: R489.1 ; also on sheet 14
MPC_FEC3_CRS: R336.2 ; also on sheet 14
MPC_FEC3_RXCLK: R335.2 ; also on sheet 14
MPC_FEC3_RXD0: R462.2 ; also on sheet 14
MPC_FEC3_RXD1: R461.2 ; also on sheet 14
MPC_FEC3_RXD2: R460.2 ; also on sheet 14
MPC_FEC3_RXD3: R464.2 ; also on sheet 14
MPC_FEC3_RXDV: R463.2 ; also on sheet 14
MPC_FEC3_RXER: R490.1 ; also on sheet 14
MPC_FEC3_TXCLK: R302.1 ; also on sheet 14
MPC_FEC3_TXD0: R396.1 ; also on sheet 14
MPC_FEC3_TXD1: R395.1 ; also on sheet 14
MPC_FEC3_TXD2: R394.1 ; also on sheet 14
MPC_FEC3_TXD3: R393.1 ; also on sheet 14
MPC_FEC3_TXEN: R304.1 ; also on sheet 14
MPC_FEC3_TXER: R305.1 ; also on sheet 14
MPC_FEC_MDC: R316.2 ; also on sheet 7 14
MPC_FEC_MDIO: R317.2 ; also on sheet 7 14
MPC_HDLC1_CD#: R488.1 ; also on sheet 12
MPC_HDLC1_CTS#: R457.2 ; also on sheet 12
MPC_HDLC1_RCK: R347.2 ; also on sheet 12
MPC_HDLC1_RTS#_BOOT_CFG1: R456.1 ; also on sheet 8 12
MPC_HDLC1_RXD: R383.2 ; also on sheet 12
MPC_HDLC1_TCK: R346.2 ; also on sheet 12
MPC_HDLC1_TXD_BOOT_CFG0: R379.2 ; also on sheet 8 12
MPC_HDLC2_CD#: R405.2 ; also on sheet 12
MPC_HDLC2_CTS#: R384.2 ; also on sheet 12
MPC_HDLC2_RCK: R437.2 ; also on sheet 12
MPC_HDLC2_RTS#_BOOT_CFG3: R385.2 ; also on sheet 8 12
MPC_HDLC2_RXD: R406.2 ; also on sheet 12
MPC_HDLC2_TCK: R436.2 ; also on sheet 12
MPC_HDLC2_TXD_BOOT_CFG2: R412.2 ; also on sheet 8 12
MPC_HRESET#: R321.2 U9.1(I0) ; also on sheet 7 8 15
MPC_I2C1_SCL: R314.2 ; also on sheet 13
MPC_I2C1_SDA: R315.2 ; also on sheet 13
MPC_I2C2_SCL: J30.18(SCL) R414.1 U12.29(CTRL_CLK) ; also on sheet 13 15
MPC_I2C2_SDA: J30.16(SDA) R415.1 U12.27(CTRL_DATA) ; also on sheet 13 15
MPC_LBC_ADD0: R427.1 ; also on sheet 13
MPC_LBC_ADD1: R426.1 ; also on sheet 10 13
MPC_LBC_ADD2: R425.1 ; also on sheet 10 13
MPC_LBC_ADD3: R337.1 ; also on sheet 10 13
MPC_LBC_ADD4: R325.1 ; also on sheet 10 13
MPC_LBC_ADD5: R320.1 ; also on sheet 10 13
MPC_LBC_ADD6: J11.B70(FB_AD19) ; also on sheet 10 13
MPC_LBC_ADD7: J11.B69(FB_AD18) ; also on sheet 10 13
MPC_LBC_ADD8: J11.B68(FB_AD17) ; also on sheet 10 13
MPC_LBC_ADD9: J11.B67(FB_AD16) ; also on sheet 10 13
MPC_LBC_ADD10: J11.B66(FB_AD15) ; also on sheet 10 13
MPC_LBC_ADD11: J11.A66(FB_AD14) ; also on sheet 10 13
MPC_LBC_ADD12: J11.A67(FB_AD13) ; also on sheet 10 13
MPC_LBC_ADD13: J11.A68(FB_AD12) ; also on sheet 10 13
MPC_LBC_ADD14: J11.A69(FB_AD11) ; also on sheet 10 13
MPC_LBC_ADD15: J11.A70(FB_AD10) ; also on sheet 10 13
MPC_LBC_ADD16: J11.A71(FB_AD9) ; also on sheet 10 13
MPC_LBC_ADD17: J11.A72(FB_AD8) ; also on sheet 10 13
MPC_LBC_ADD18: J11.A73(FB_AD7) ; also on sheet 10 13
MPC_LBC_ADD19: J11.A74(FB_AD6) ; also on sheet 10 13
MPC_LBC_ADD20: J11.A75(FB_AD5) ; also on sheet 10 13
MPC_LBC_ADD21: J11.A76(FB_AD4) ; also on sheet 10 13
MPC_LBC_ADD22: J11.A77(FB_AD3) ; also on sheet 10 13
MPC_LBC_ADD23: J11.A78(FB_AD2) ; also on sheet 10 13
MPC_LBC_ADD24: J11.A79(FB_AD1) J30.10(ADDR) ; also on sheet 10 13
MPC_LBC_ADD25: J11.A80(FB_AD0) ; also on sheet 13
MPC_LBC_ALE: J11.B63(FB_ALE/FB_CS1_B) R420.2 ; also on sheet 13
MPC_LBC_CLE: R421.2 ; also on sheet 13
MPC_LBC_CS0#: R424.2 R442.2 R495.1 ; also on sheet 8 13
MPC_LBC_CS2#: J30.8(Parallel_CS#) ; also on sheet 13
MPC_LBC_CS3#: R419.1 ; also on sheet 13
MPC_LBC_D0: J11.B73(FB_D7) J30.37(D17) ; also on sheet 13
MPC_LBC_D1: J11.B74(FB_D6) J30.35(D16) ; also on sheet 13
MPC_LBC_D2: J11.B75(FB_D5) J30.33(D15) ; also on sheet 13
MPC_LBC_D3: J11.B76(FB_D4) J30.31(D14) ; also on sheet 13
MPC_LBC_D4: J11.B77(FB_D3) J30.29(D13) ; also on sheet 13
MPC_LBC_D5: J11.B78(FB_D2) J30.27(D12) ; also on sheet 13
MPC_LBC_D6: J11.B79(FB_D1) J30.25(D11) ; also on sheet 13
MPC_LBC_D7: J11.B80(FB_D0) J30.23(D10) ; also on sheet 13
MPC_LBC_D8: J30.19(D8) ; also on sheet 13
MPC_LBC_D9: J30.17(D7) ; also on sheet 13
MPC_LBC_D10: J30.15(D6) ; also on sheet 13
MPC_LBC_D11: J30.13(D5) ; also on sheet 13
MPC_LBC_D12: J30.11(D4) ; also on sheet 13
MPC_LBC_D13: J30.9(D3) ; also on sheet 13
MPC_LBC_D14: J30.7(D2) ; also on sheet 13
MPC_LBC_D15: J30.5(D1) ; also on sheet 13
MPC_LBC_GPL5: R423.2 ; also on sheet 13
MPC_LBC_RB#: R311.2 ; also on sheet 13
MPC_LBC_RE/OE#: J11.B72(FB_OE_B) ; also on sheet 10 13
MPC_LBC_WE0#: J11.B71(FB_R/W_B) J30.4(WR#) R303.2 ; also on sheet 10 13
MPC_LBC_WE1#: R301.2 ; also on sheet 13
MPC_LBC_WP#: R422.2 ; also on sheet 13
MPC_LBCTL: R407.1 ; also on sheet 13
MPC_LCK0: R401.1 ; also on sheet 13 14
MPC_OB_SPI_CLK: J11.B48(SPI0_CLK) J30.26(SPI_CLK) ; also on sheet 13 15
MPC_OB_SPI_MISO: J11.B44(SPI0_MISO) J30.28(SPI_MISO) ; also on sheet 13 15
MPC_OB_SPI_MOSI: J11.B45(SPI0_MOSI) J30.24(SPI_MOSI) ; also on sheet 13 15
MPC_PCI_AD0: J14.B45(LCD_D0/LCD0) ; also on sheet 11
MPC_PCI_AD1: J14.B46(LCD_D1/LCD1) ; also on sheet 11
MPC_PCI_AD2: J14.B47(LCD_D2/LCD2) ; also on sheet 11
MPC_PCI_AD3: J14.B48(LCD_D3/LCD3) ; also on sheet 11
MPC_PCI_AD4: J14.A50(LCD_D4/LCD4) ; also on sheet 11
MPC_PCI_AD5: J14.A51(LCD_D5/LCD5) ; also on sheet 11
MPC_PCI_AD6: J14.A52(LCD_D6/LCD6) ; also on sheet 11
MPC_PCI_AD7: J14.A53(LCD_D7/LCD7) ; also on sheet 11
MPC_PCI_AD8: J14.A54(LCD_D8/LCD8) ; also on sheet 11
MPC_PCI_AD9: J14.A55(LCD_D9/LCD9) ; also on sheet 11
MPC_PCI_AD10: J14.A56(LCD_D10/LCD10) ; also on sheet 11
MPC_PCI_AD11: J14.A57(LCD_D11/LCD11) ; also on sheet 11
MPC_PCI_AD12: J14.B52(LCD_D12/LCD12) ; also on sheet 11
MPC_PCI_AD13: J14.B53(LCD_D13/LCD13) ; also on sheet 11
MPC_PCI_AD14: J14.B54(LCD_D14/LCD14) ; also on sheet 11
MPC_PCI_AD15: J14.A62(LCD_D15/LCD15) ; also on sheet 11
MPC_PCI_AD16: J14.A63(LCD_D16/LCD16) ; also on sheet 11
MPC_PCI_AD17: J14.A64(LCD_D17/LCD17) ; also on sheet 11
MPC_PCI_AD18: J14.B63(LCD_D18/LCD18) ; also on sheet 11
MPC_PCI_AD19: J14.B64(LCD_D19/LCD19) ; also on sheet 11
MPC_PCI_AD20: J14.B78(LCD_D20/LCD20) ; also on sheet 11
MPC_PCI_AD21: J14.B79(LCD_D21/LCD21) ; also on sheet 11
MPC_PCI_AD22: J14.B80(LCD_D22/LCD22) ; also on sheet 11
MPC_PCI_AD23: J14.A80(LCD_D23/LCD23) ; also on sheet 11
MPC_PCI_AD24: R474.1 ; also on sheet 11
MPC_PCI_AD25: R475.1 ; also on sheet 11
MPC_PCI_AD26: J14.B72(FB_AD26/LCD48) ; also on sheet 11
MPC_PCI_AD27: J14.B73(FB_AD27/LCD49) ; also on sheet 11
MPC_PCI_AD28: J14.B74(FB_AD28/LCD50) ; also on sheet 11
MPC_PCI_AD29: J14.B75(FB_AD29/LCD51) ; also on sheet 11
MPC_PCI_AD30: J14.B76(FB_AD30/LCD52) ; also on sheet 11
MPC_PCI_AD31: J14.B77(FB_AD31/LCD53) ; also on sheet 11
MPC_PCI_CBE0#: R477.2 ; also on sheet 11
MPC_PCI_CBE1#: R476.2 ; also on sheet 11
MPC_PCI_CBE2#: R465.1 ; also on sheet 11
MPC_PCI_CBE3#: R466.1 ; also on sheet 11
MPC_PCI_CLK0: R440.1 ; also on sheet 11
MPC_PCI_CLK1: R439.1 ; also on sheet 11
MPC_PCI_CLK2: R438.1 ; also on sheet 11
MPC_PCI_DEVSEL#: R470.1 ; also on sheet 11
MPC_PCI_FRAME#: R480.2 ; also on sheet 11
MPC_PCI_GNT0#: R443.1 R446.1 R447.1 ; also on sheet 11
MPC_PCI_GNT1#: R444.1 ; also on sheet 11
MPC_PCI_GNT2#: R445.1 ; also on sheet 11
MPC_PCI_IDSEL#: R472.1 ; also on sheet 11
MPC_PCI_INTA#: R479.2 ; also on sheet 11 13
MPC_PCI_IRDY#: R469.1 ; also on sheet 11
MPC_PCI_M66EN: J14.B44(LCD_OE/LCD27) ; also on sheet 11
MPC_PCI_PAR: R481.2 ; also on sheet 11
MPC_PCI_PERR#: R473.1 ; also on sheet 11
MPC_PCI_REQ0#: R448.2 R451.2 R452.2 ; also on sheet 11
MPC_PCI_REQ1#: R449.2 ; also on sheet 11
MPC_PCI_REQ2#: R450.2 ; also on sheet 11
MPC_PCI_RST_OUT#: R478.2 ; also on sheet 11
MPC_PCI_SERR#: R471.1 ; also on sheet 11
MPC_PCI_STOP#: R468.1 ; also on sheet 11
MPC_PCI_SYNC_IN: R413.2 R428.2 ; also on sheet 11
MPC_PCI_TRDY#: R467.1 ; also on sheet 11
MPC_QE_CLK_IN: R399.1 ; also on sheet 8
MPC_RST_TWR#: U9.2(I1) ; also on sheet 13
MPC_SD_DATA0: R103.1 U1.D4(GPIO_4/SD_DAT0/MSRCID4_(DDR_ID))
MPC_SD_DATA1: R104.1 U1.C4(GPIO_5/SD_DAT1/MDVAL_(DDR_ID))
MPC_SD_DATA2: R105.1 U1.B2(GPIO_6/SD_DAT2/QE_EXT_REQ_3)
MPC_SD_DATA3: R106.1 U1.B3(GPIO_7/SD_DAT3/QE_EXT_REQ_1)
MPC_SPI_SEL_BOOT#: R404.1 ; also on sheet 13
MPC_TMR_GCLK: R485.1 ; also on sheet 14 15
MPR121_2_MPC_IRQ#: J30.22(IRQ#) ; also on sheet 13
OB_2_MPC_CF_SPI_IRQ#: J11.B58(IRQ_E) ; also on sheet 13
OB_2_MPC_I2C_IRQ#: J11.B59(IRQ_D) ; also on sheet 13
OB_2_MPC_SPI0_IRQ#: J11.B55(IRQ_H) ; also on sheet 13
OB_2_MPC_SPI1_IRQ#: J11.B56(IRQ_G) ; also on sheet 13
OB_2_MPC_SPI2_IRQ#: J11.B57(IRQ_F) ; also on sheet 13
OB_BOOT_CONFIG0: R492.2 ; also on sheet 8
OB_BOOT_CONFIG1: R491.2 ; also on sheet 8
OB_BOOT_CONFIG2: R494.2 ; also on sheet 8
OB_BOOT_CONFIG3: R493.2 ; also on sheet 8
OB_DRV_NOR_LCS#: R424.1 R441.2 ; also on sheet 8
SD_CD#: J3.11(nCD) R101.2 R112.2 R118.1
SD_CLK: J3.5(CLK) R99.2 R109.2 R375.1
SD_CMD: J3.2(CMD) R100.2 R377.1
SD_DATA0: J3.7(DAT0) R103.2 R108.2 R117.1 R378.1
SD_DATA1: J3.8(DAT1) R104.2 R107.2 R398.1
SD_DATA2: J3.9(DAT2) R105.2 R111.2 R312.2
SD_DATA3: J3.1(CD/DAT3) R106.2 R110.2 R376.1
SD_WP: J3.10(WP) R102.2 R113.2 R119.1 R313.2
SDATAIN: U12.25(I2S_DOUT) ; also on sheet 15
SDATAOUT: U12.26(I2S_DIN) ; also on sheet 15
SYNC: U12.23(I2S_LRCLK) ; also on sheet 15
SYS_MCLK: R487.1 ; also on sheet 8
TEP_UART1_CTS#: R453.2 R458.2 ; also on sheet 12
TEP_UART1_RTS#: R454.2 R455.1 ; also on sheet 12
TEP_UART1_RXD: R433.1 R434.2 ; also on sheet 12
TEP_UART1_TXD: R432.1 R435.2 ; also on sheet 12
THERM0: R386.2 ; also on sheet 8
TWR_RESET#: R322.2 R392.2 U9.4(O)
N19036614: R17.1 U1.D15(GPIO_12/RXCAN3/LSRCID4/LCLK1)
N20980607: J11.B14(ETH_TXCLK/ETH_REF_CLK) R302.2
N20981173: J11.B64(FB_CS0_B) R419.2 R495.2
N20981307: J11.A64(CLKOUT0) R428.1
N22418867: D5.2(ANODE) FB22.2
N22418929: R338.1 R341.2 U41.1(FB)
N22418931: C283.1 L4.2 U41.3(SW1) U41.8(SW2)
N22419122: R332.1 R333.2 U40.1(FB)
N22419269: R331.1 U40.6(PG)
N22419467: R326.1 U39.6(PG)
N22495761: C283.2 U41.5(BS)
N22515283: C277.1 L3.2 U40.3(SW1) U40.8(SW2)
N22519196: C277.2 U40.5(BS)
N22524999: C270.2 U39.5(BS)
N22525213: C270.1 L2.2 U39.3(SW1) U39.8(SW2)
N22526732: R329.1 R330.2 U39.1(FB)
N22678056: J11.B7(SPI1_CLK) R375.2
N22678060: J11.B11(SPI1_MISO) R378.2
N22678070: J11.B10(SPI1_MOSI) R377.2
N23550848: D8.1(ANODE) R328.1
N23551941: D7.1(ANODE) R327.1
N25499370: R340.1 U41.10(EN/SYNC)
N31449252: J11.B15(ETH_TXEN) R304.2
N31711931: J11.A10(GPIO8/OPEN) R312.1
N31711943: J11.A11(GPIO7/OPEN) R313.1
N34682104: J11.B8(SPI1_CS1) R376.2
N34724943: J11.B17(ETH_TXD3) R393.2
N34724953: J11.B16(ETH_TXER) R305.2
N34727576: J11.B19(ETH_TXD1) R395.2
N34727586: J11.B18(ETH_TXD2) R394.2
N34730196: J11.B20(ETH_TXD0) R396.2
N34741531: J11.B23(GPIO3/OPEN) R397.2
N34741543: J11.B22(GPIO2/OPEN) R398.2
N34761168: J11.B24(CLKIN0) R399.2
N34782343: J11.B25(CLKOUT1) R400.2 R401.2
N34844610: J11.B43(CAN) R402.2
N34853491: J11.B46(SPI0_CS0) R403.2 R404.2
N36245819: J11.B32(DAC1) R407.2
N36396883: J11.A56(USB_ID) R301.1
N36396887: J11.A57(USB_VBUS) R303.1
N36398546: J11.A54(USB_DM) R309.1
N36398550: J11.A55(USB_DP) R310.1
N36420600: J11.A46(GPIO02) R311.1
N36827123: J11.A7(SCL0) R314.1
N36827127: J11.A8(SDA0) R315.1
N36831753: J11.B50(SCL1) R414.2
N36834717: J11.B51(SDA1) R415.2
N36922217: J11.A13(ETH_MDC) R316.1
N36922221: J11.A14(ETH_MDIO) R317.1
N38190723: C357.2 U12.11(LINEOUT_R)
N38190741: C358.2 U12.12(LINEOUT_L)
N38190758: C326.1 U12.15(MIC)
N38190762: C360.1 U12.13(LINEIN_R)
N38190784: C359.1 U12.14(LINEIN_L)
N38190796: C356.2 U12.10(VAG)
N39129555: J11.B53(USB_DP_PDOWN) R432.2
N39129567: J11.B54(USB_DM_PDOWN) R433.2
N39220107: J11.A52(GPIO07) R346.1
N39220111: J11.A53(TMS/BKPT_B) R347.1
N39225286: J11.A43(RXD1) R379.1 R435.1
N39228359: J11.A44(TXD1) R383.1 R434.1
N39230100: J11.A45(GPIO01) R384.1
N39231843: J11.A47(GPIO03) R385.1
N39234925: J11.A48(GPIO04) R386.1
N39286995: J11.A23(SSI_FS) R405.1
N39286999: J11.A24(SSI_RXD) R406.1
N39287019: J11.A25(SSI_TXD) R412.1
N39287031: J11.A21(SSI_MCLK) R437.1
N39287035: J11.A22(SSI_BCLK) R436.1
N39739173: J11.A62(RSTIN_B) R321.1
N39739177: J11.A63(RSTOUT_B) R322.1
N39940946: J11.B21(GPIO1/OPEN) R455.2 R456.2
N40377923: J11.A18(ETH_RXD2) R460.1
N40377927: J11.A19(ETH_RXD1) R461.1
N40377939: J11.A20(ETH_RXD0) R462.1
N40377951: J11.A16(ETH_RXDV/ETH_CRS_DV) R463.1
N40377955: J11.A17(ETH_RXD3) R464.1
N40379708: J11.A15(ETH_RXCLK) R335.1
N40382744: J11.A12(ETH_CRS) R336.1
N40576193: R485.2 R487.2 U12.21(SYS_MCLK)
N40800179: J14.A70(FB_TSIZE0/LCD32) R420.1
N40800181: J14.A38(PWM10) R478.1
N40800185: J14.A37(PWM11) R479.1
N40800400: J14.B35(GPIO4/OPEN) R466.2
N40800412: J14.B66(FB_AD20/LCD42) R320.2
N40800584: J14.B58(IRQ_E) R443.2
N40800617: J14.A59(TMR15) R449.1 R451.1
N40800623: J14.B59(IRQ_D) R444.2 R447.2
N40800633: J14.A40(PWM8) R480.1
N40800637: J14.A39(PWM9) R481.1
N40800681: J14.B27(LCD_HSYNC/LCD24) R438.2
N40800689: J14.B43(GPIO06) R473.2
N40800783: J14.B67(FB_AD21/LCD43) R325.2
N40800795: J14.A71(FB_TSIZE1/LCD33) R421.1
N40800810: J14.A60(TMR14) R450.1 R452.1
N40800814: J14.B28(LCD_VSYNC/LCD24) R439.2
N40800880: J14.B37(PWM15) R467.2
N40800907: J14.A77(FB_CS2/LCD39) R441.1
N40800913: J14.B68(FB_AD22/LCD44) R337.2
N40800915: J14.B69(FB_AD23/LCD45) R425.2
N40800938: J14.B60(IRQ_C) R445.2 R446.2
N40800946: J14.B32(LCD_CLK/LCD26) R440.2
N40800989: J14.A72(FB_TS/LCD34) R422.1
N40801038: J14.A35(GPIO6/OPEN) R476.1
N40801042: J14.A34(TMR8) R477.1
N40801064: J14.B39(PWM13) R468.2
N40801072: J14.B38(PWM14) R469.2
N40801134: J14.B70(FB_AD24/LCD46) R426.2
N40801136: J14.B71(FB_AD25/LCD47) R427.2
N40801181: J14.A32(GPIO03) R413.1
N40801243: J14.B34(TMR10) R465.2
N40801281: J14.A73(FB_TBST/LCD35) R423.1
N40801330: J14.A78(FB_CS1/LCD40) R442.1
N40801411: J14.B40(PWM12) R470.2
N40801423: J14.B42(CANTX) R471.2
N40801427: J14.B41(CANRX) R472.2
N40801455: J14.B50(GPIO05) R474.2
N40801465: J14.B51(GPIO04) R475.2
N40801493: J14.A58(TMR16) R448.1
N42208569: J11.B9(SPI1_CS0) R488.2
N42211865: J11.B12(ETH_COL) R489.2
N42215164: J11.B13(ETH_RXER) R490.2
N42432967: J14.A67(FB_BE2/LCD29) R491.1
N42432969: J14.A66(FB_BE3/LCD28) R492.1
N42432987: J14.A69(FB_BE0/LCD31) R493.1
N42432989: J14.A68(FB_BE1/LCD30) R494.1
N42588884: J11.A41(RXD0) R453.1
N42605584: J11.A9(GPIO9/OPEN) R457.1 R458.1
N42623561: J11.A42(TXD0) R454.1
N44114808: D19.2(ANODE) U32.6(OUT1) U32.8(OUT2)
N44127665: D20.2(ANODE) U34.6(OUT1) U34.8(OUT2)
N44169986: Q8.3(COLLECTOR) R298.2 U32.1(CTL) U34.1(CTL)
N44380330: Q8.1(BASE) R297.1

Not connected (* = marked no-connect by the designer): J14 A7(SCL0)* A8(SDA0)* A9(GPIO9/OPEN)* A10(USB_SOTP)* A11(USB_CLK)* A12(GPIO) A13(ETH_MDC) A14(ETH_MDIO) A15(ETH_RXCLK) A16(ETH_RXDV/ETH_CRS_DV) A17(GPIO01) A18(GPIO02) A19(ETH_RXD1) A20(ETH_RXD0) A21(USB_DATA0)* A22(USB_DATA1)* A23(USB_DATA2)* A24(USB_DATA3)* A25(USB_DATA4)* A27(AN11) A28(AN10) A29(AN9) A30(AN8) A33(TMR9)* A41(RXD2)* A42(TXD2)* A43(RTS2)* A44(CTS2)* A45(RXD3)* A46(TXD3)* A47(RST3)* A48(CST3)* A61(TMR13)* A74(FB_TA/LCD36) A75(FB_CS4/LCD37) A76(FB_CS3/LCD38) A79(GPIO/LCD41)* B7(SPI1_CLK)* B8(SPI1_CS1)* B9(SPI1_CS0)* B10(SPI1_MOSI)* B11(SPI1_MISO)* B12(ETH_COL) B13(ETH_RXER) B14(ETH_TXCLK/ETH_REF_CLK) B15(ETH_TXEN) B16(ETH_TXER)* B17(GPIO08) B18(GPIO07) B19(ETH_TXD1) B20(ETH_TXD0) B21(USB1_NEXT)* B22(USB1_DIR)* B23(USB_DATA5)* B24(USB_DATA6)* B25(USB_DATA7)* B29(AN13) B30(AN12) B33(TMR11)* B55(IRQ_H)* B56(IRQ_G)* B57(IRQ_F)* B61(IRQ_B)* B62(IRQ_A)*; J18 4*; J26 2; J30 6(OE#)*; U1 A23(NC)*; U12 8(NC1)* 9(NC2)* 17(NC3)* 18(CPFILT)* 19(NC4)* 22(NC5)* 28(NC6)* 30(VDDD)*; U32 2(FLG)* 4(GATE)*; U34 2(FLG)* 4(GATE)*

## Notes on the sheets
sheet 1
- Power Supplies
- External Power Input
- 3.3V @ 2.5A POWER SUPPLY
- 3.3V CORE SUPPLY
- Tower Power Input
- 1.8V @ 2.5A POWER SUPPLY
- 1.8V DDR-2 SUPPLY
- When ELE_PS_SENSE = 0,
  Drive on board +3.3V to +3.3V_ELEV and +5V to +5V_ELEV
  When ELE_PS_SENSE = 1,
  Disconnect +3.3V_ELEV from on board +3.3V and +5V_ELEV from +5V
- 1.0V @ 2.5A POWER SUPPLY
- 1.0V CORE SUPPLY
- Power-up Sequence
- Voltage
- 3.3V
- 1.8V
- 1.0V
- 90%
- Time
sheet 2
- Audio CODEC
- I2C Address
  = 0x0A
- PIN25 and OIN26 SWAP
- 2.5mm Audio Jack
- 2.5mm Audio Jack
sheet 3
- TWR-MPC8309 Schematic
- SCHEMATIC PAGE DESCRIPTION:
- MAJOR REVISION HISTORY:
- 01: Cover
  02: Reset, Clock and Switch
  03: DDR2 and NOR Flash Memory
  04: eLBC, Latch, Buffer and Logics
  05: Display, SD Card and CAN
  06: Ethernet Interface and Clock
  07: Ethernet PHYs and RJ45
  08: USB Interface and USB PHY
  09: RS485, RS232 and RS232 MUX
  10: PCI Interface and Mini PCI Connector
  11: Primary and Secondary Elevators
  12: ColdFire MCU, IEEE1588, JTAG and I2C Device
  13: Audio CODEC
  14: MPC Decoupling
  15: Power Supplies
- PCB REV.
- SCM REV.
- DESCRIPTION
- DATE
- 30
- A
- Initial Version
- 4/12/2011
- 31
- B
- Production Version
- 9/14/2011
- 32
- C
- Modify Audio
- 10/26/2011
- PCB MECHANICAL DETAILS:
- 1: PCB SIZE: 90mm x 70mm
  2: PCB MATERIAL: FR4
  3: NUMBER OF LAYERS: 08
  4: IMPEDENCE CONTROL: YES
- VOLTAGE RAIL NOTATION
- PWR RAIL
- DESCRIPTION
- +5V
- 5.0V Input voltage from sources
- +5V_ELEV
- 5.0V Input/output voltage to/from tower system
- NOTES, UNLESS OTHERWISE SPECIFIED:
- +3.3V
- 3.3V MPC & Other I/O Voltage
- +3.3V_ELEV
- 3.3V Output to Tower system
- 1. RESISTANCE TOLERENCE IS 5% IF NOT SPECIFIED
  2. PARTS NOT INSTALLED ARE INDICATED WITH 'NP'.
  3. SIGNAL NET NAMES WITH "#" SUFFIX, ARE ACTIVE LOW SIGNALS.
  4. PACKAGE SIZE FOR DESCRETES IS "0402" IF NOT SPECIFIED
- +1.8V
- 1.8V MPC & DDR I/O voltage
- +1.0V
- 1.0V MPC Core Voltage
- I2C2 ADRESS DETAILS
- COMPONENT MOUNT / UNMOUNT NOTATIONS:
- 1. Audio CODEC, SGTL5000 = 0x0A
  2. Digital Accelerometer, MMA8541 = 0x1C
  3. MPR121 on Display Module = 0x5B (ADDR pin = VDD)
- NOTATION
- MOUNTING INSTRUCTIONS
- (IN "MOUNTING" PROPERTY FIELD)
- BLANK
- COMPONENT TO BE POPULATED
- NP
- NOT POPULATE
sheet 4
- MPC Decoupling
sheet 5
- Display, SD Card and CAN Signals
- Display Connector
- I2C2 Address = 0x5B
  Assume MPR121 on Display Module with ADDR pin = VDD
sheet 6
- Primary Elevator
- 0R resistor on HDLC signals
  should be placed close to MPC
- 0R resistor on HDLC signals
  should be placed close to MPC
- 0R resistor on HDLC signals
  should be placed close to MPC
- Secondary Elevator
- 0R resistor on HDLC signals
  should be placed close to MPC
